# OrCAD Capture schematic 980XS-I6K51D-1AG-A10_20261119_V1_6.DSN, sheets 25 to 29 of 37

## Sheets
25 T05.GROUP4.U5: size D
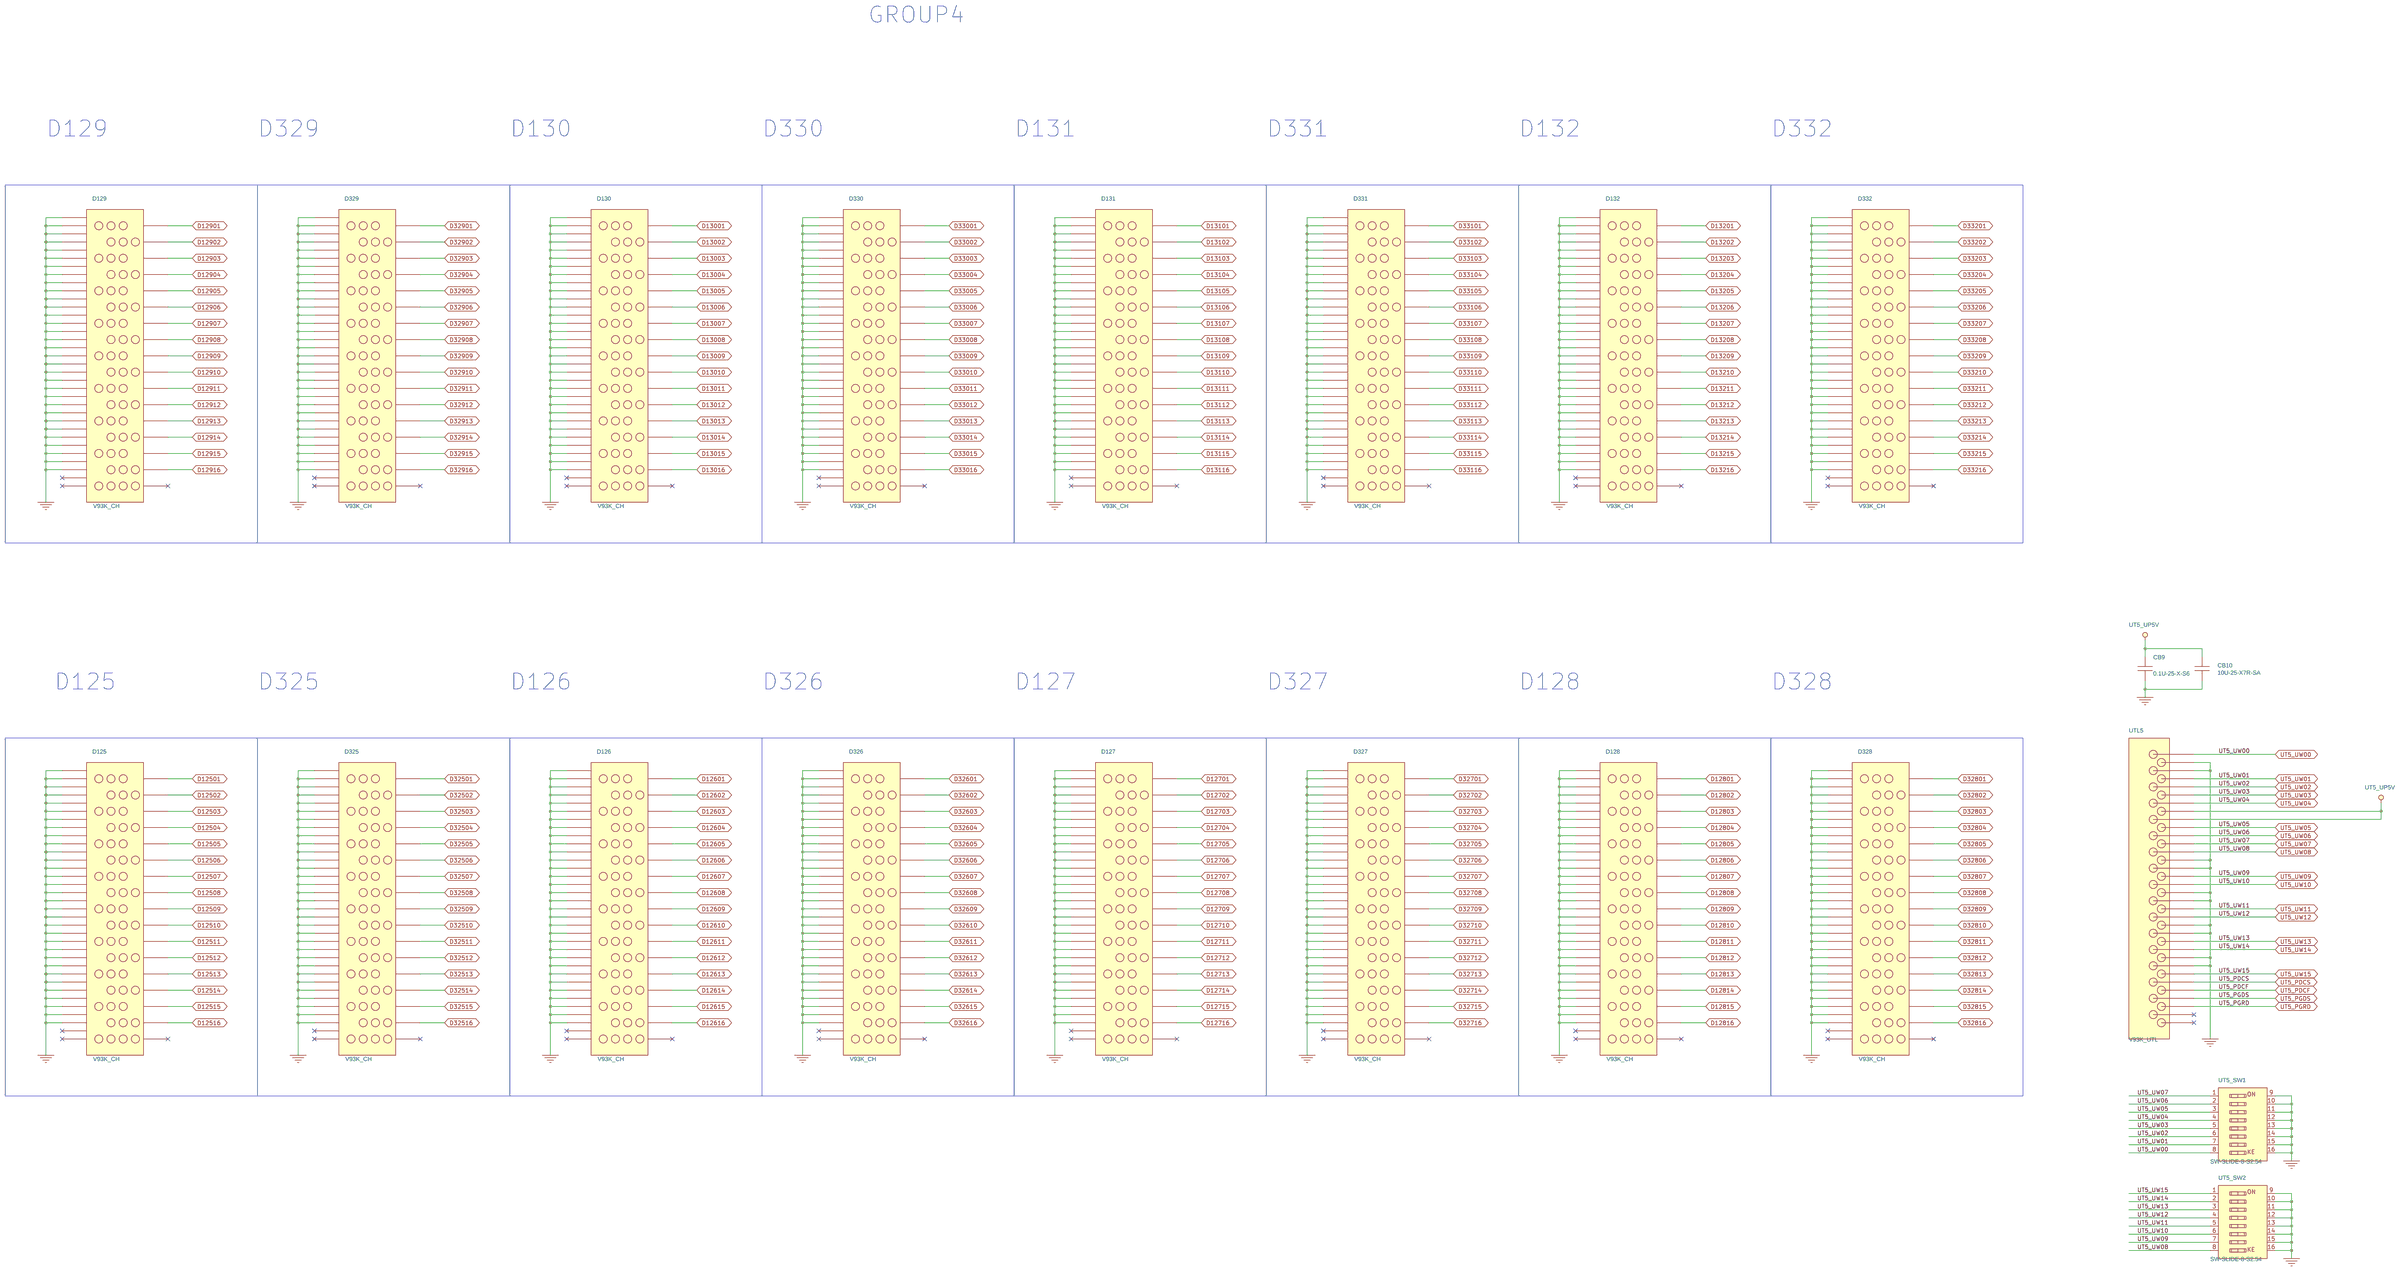
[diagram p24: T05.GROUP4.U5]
26 T06.GROUP5.U6: size D
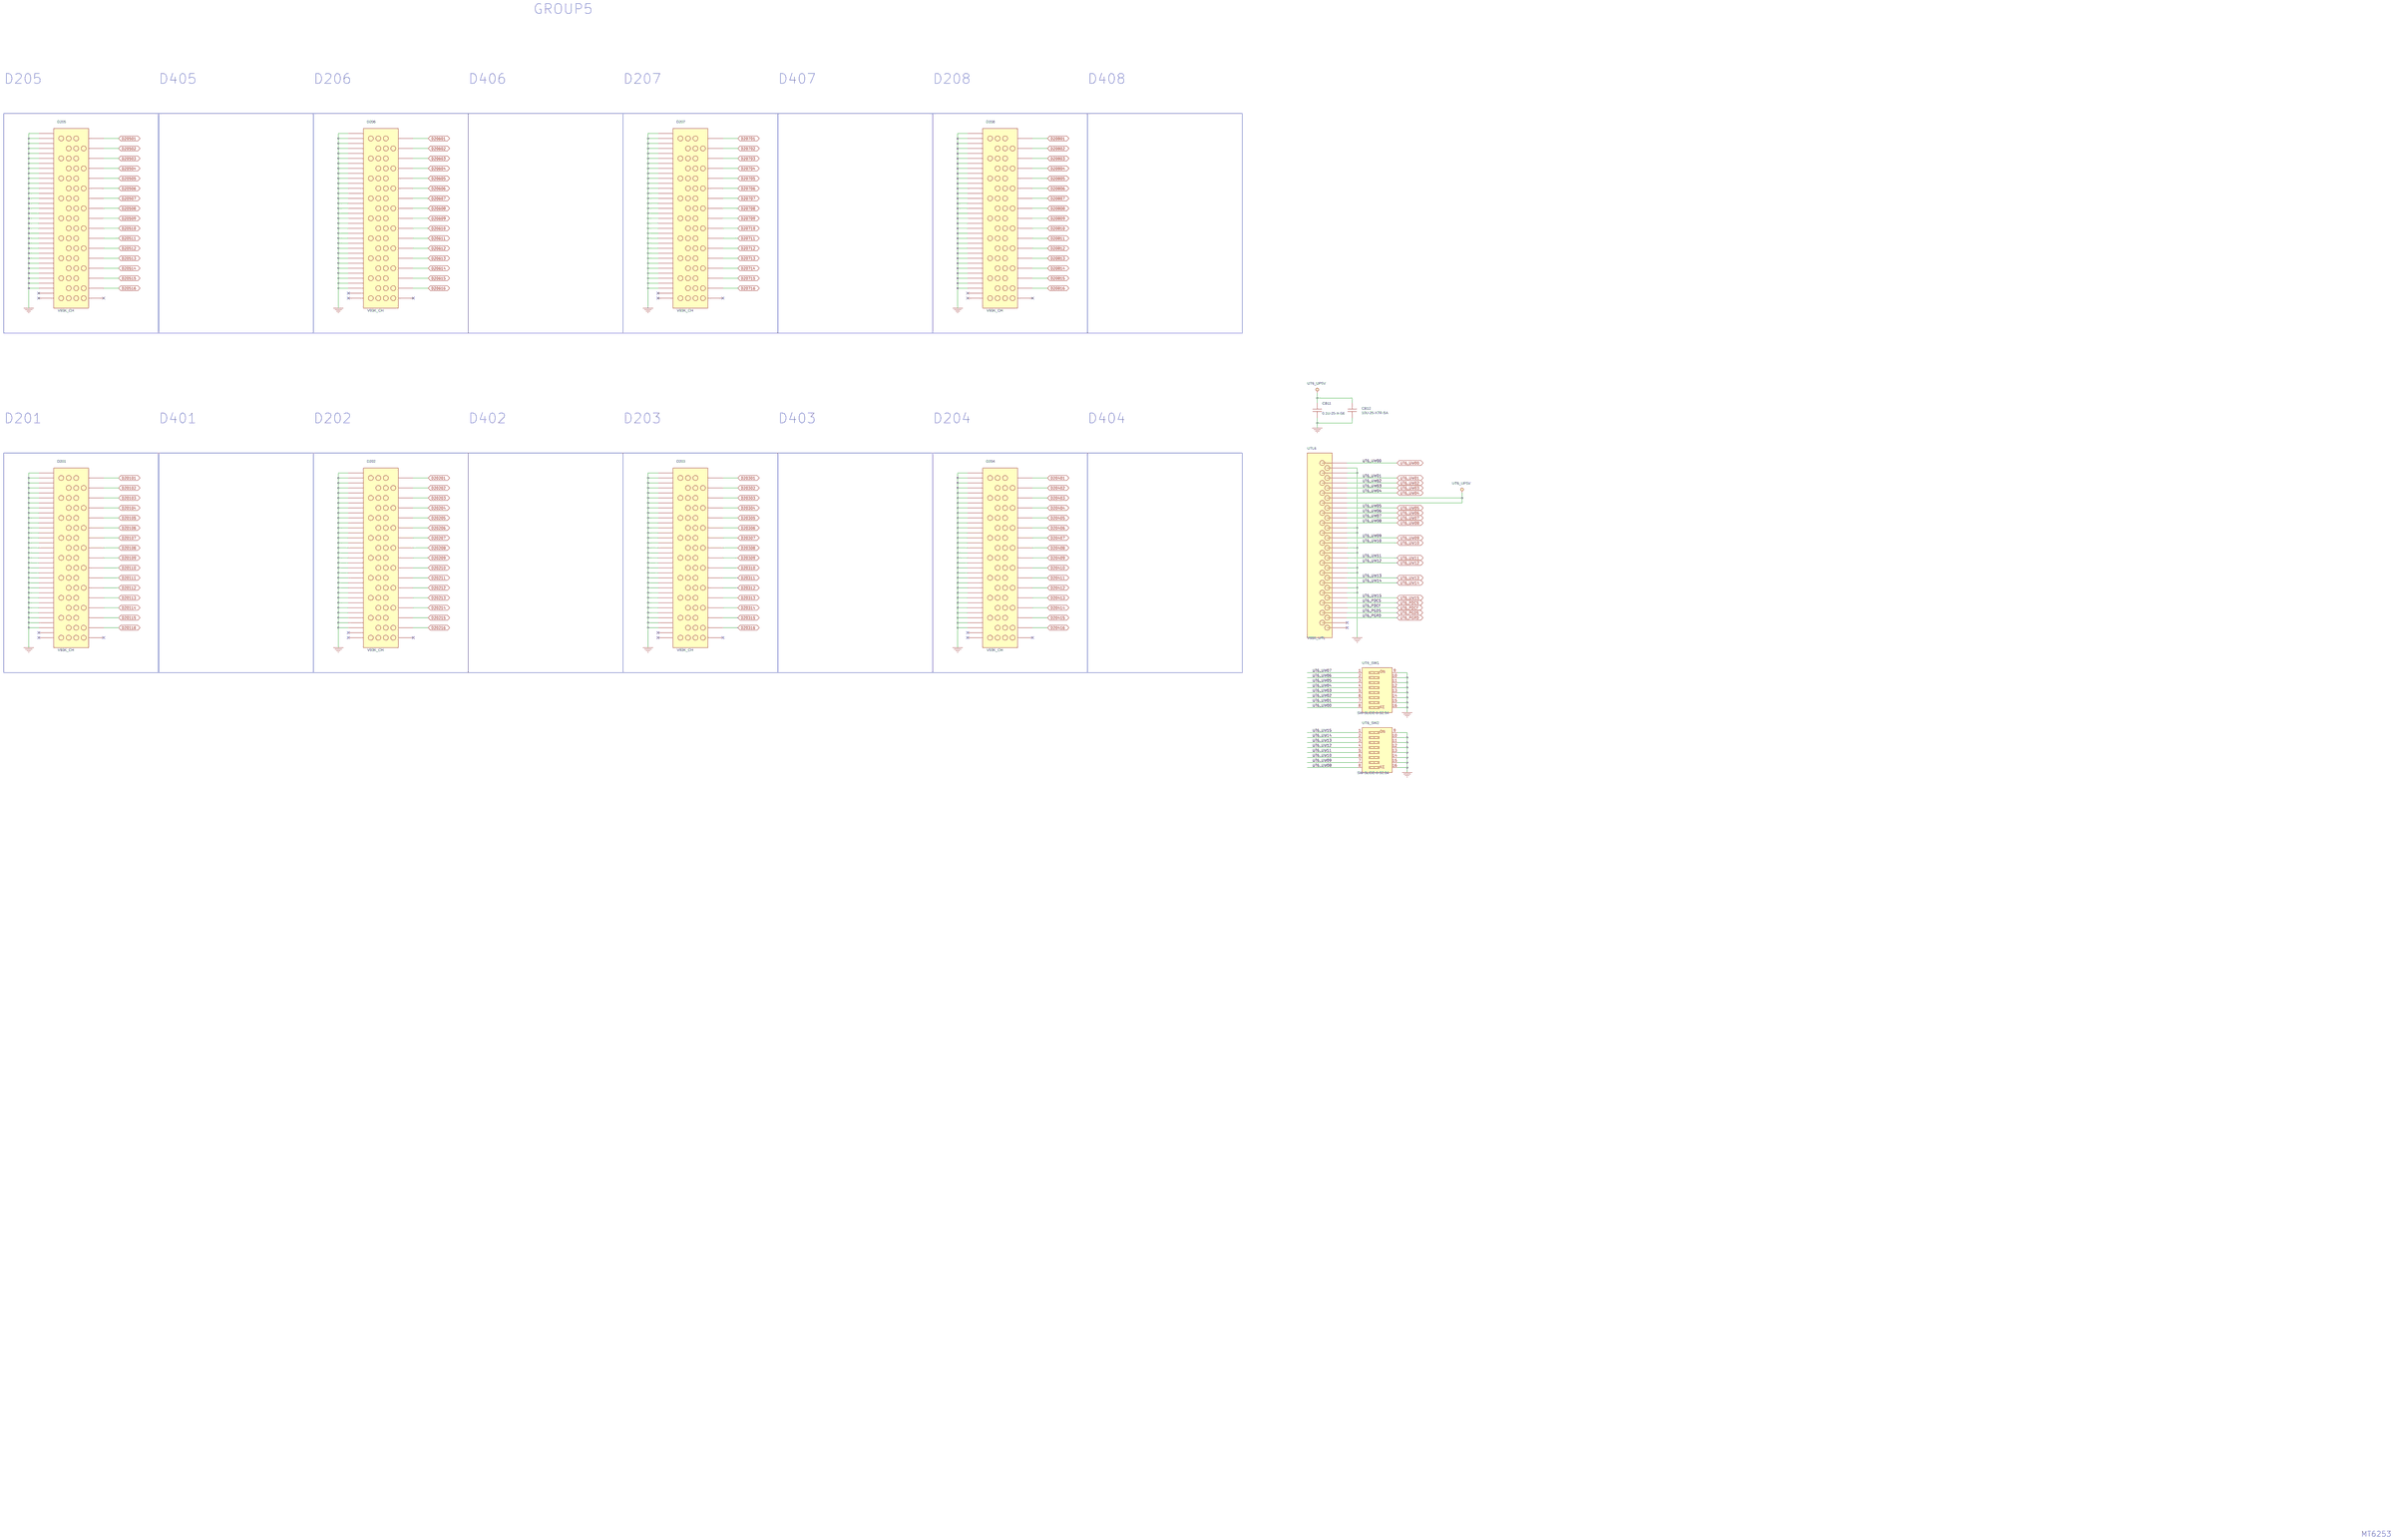
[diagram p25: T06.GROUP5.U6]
27 T07.GROUP6.U7: size D
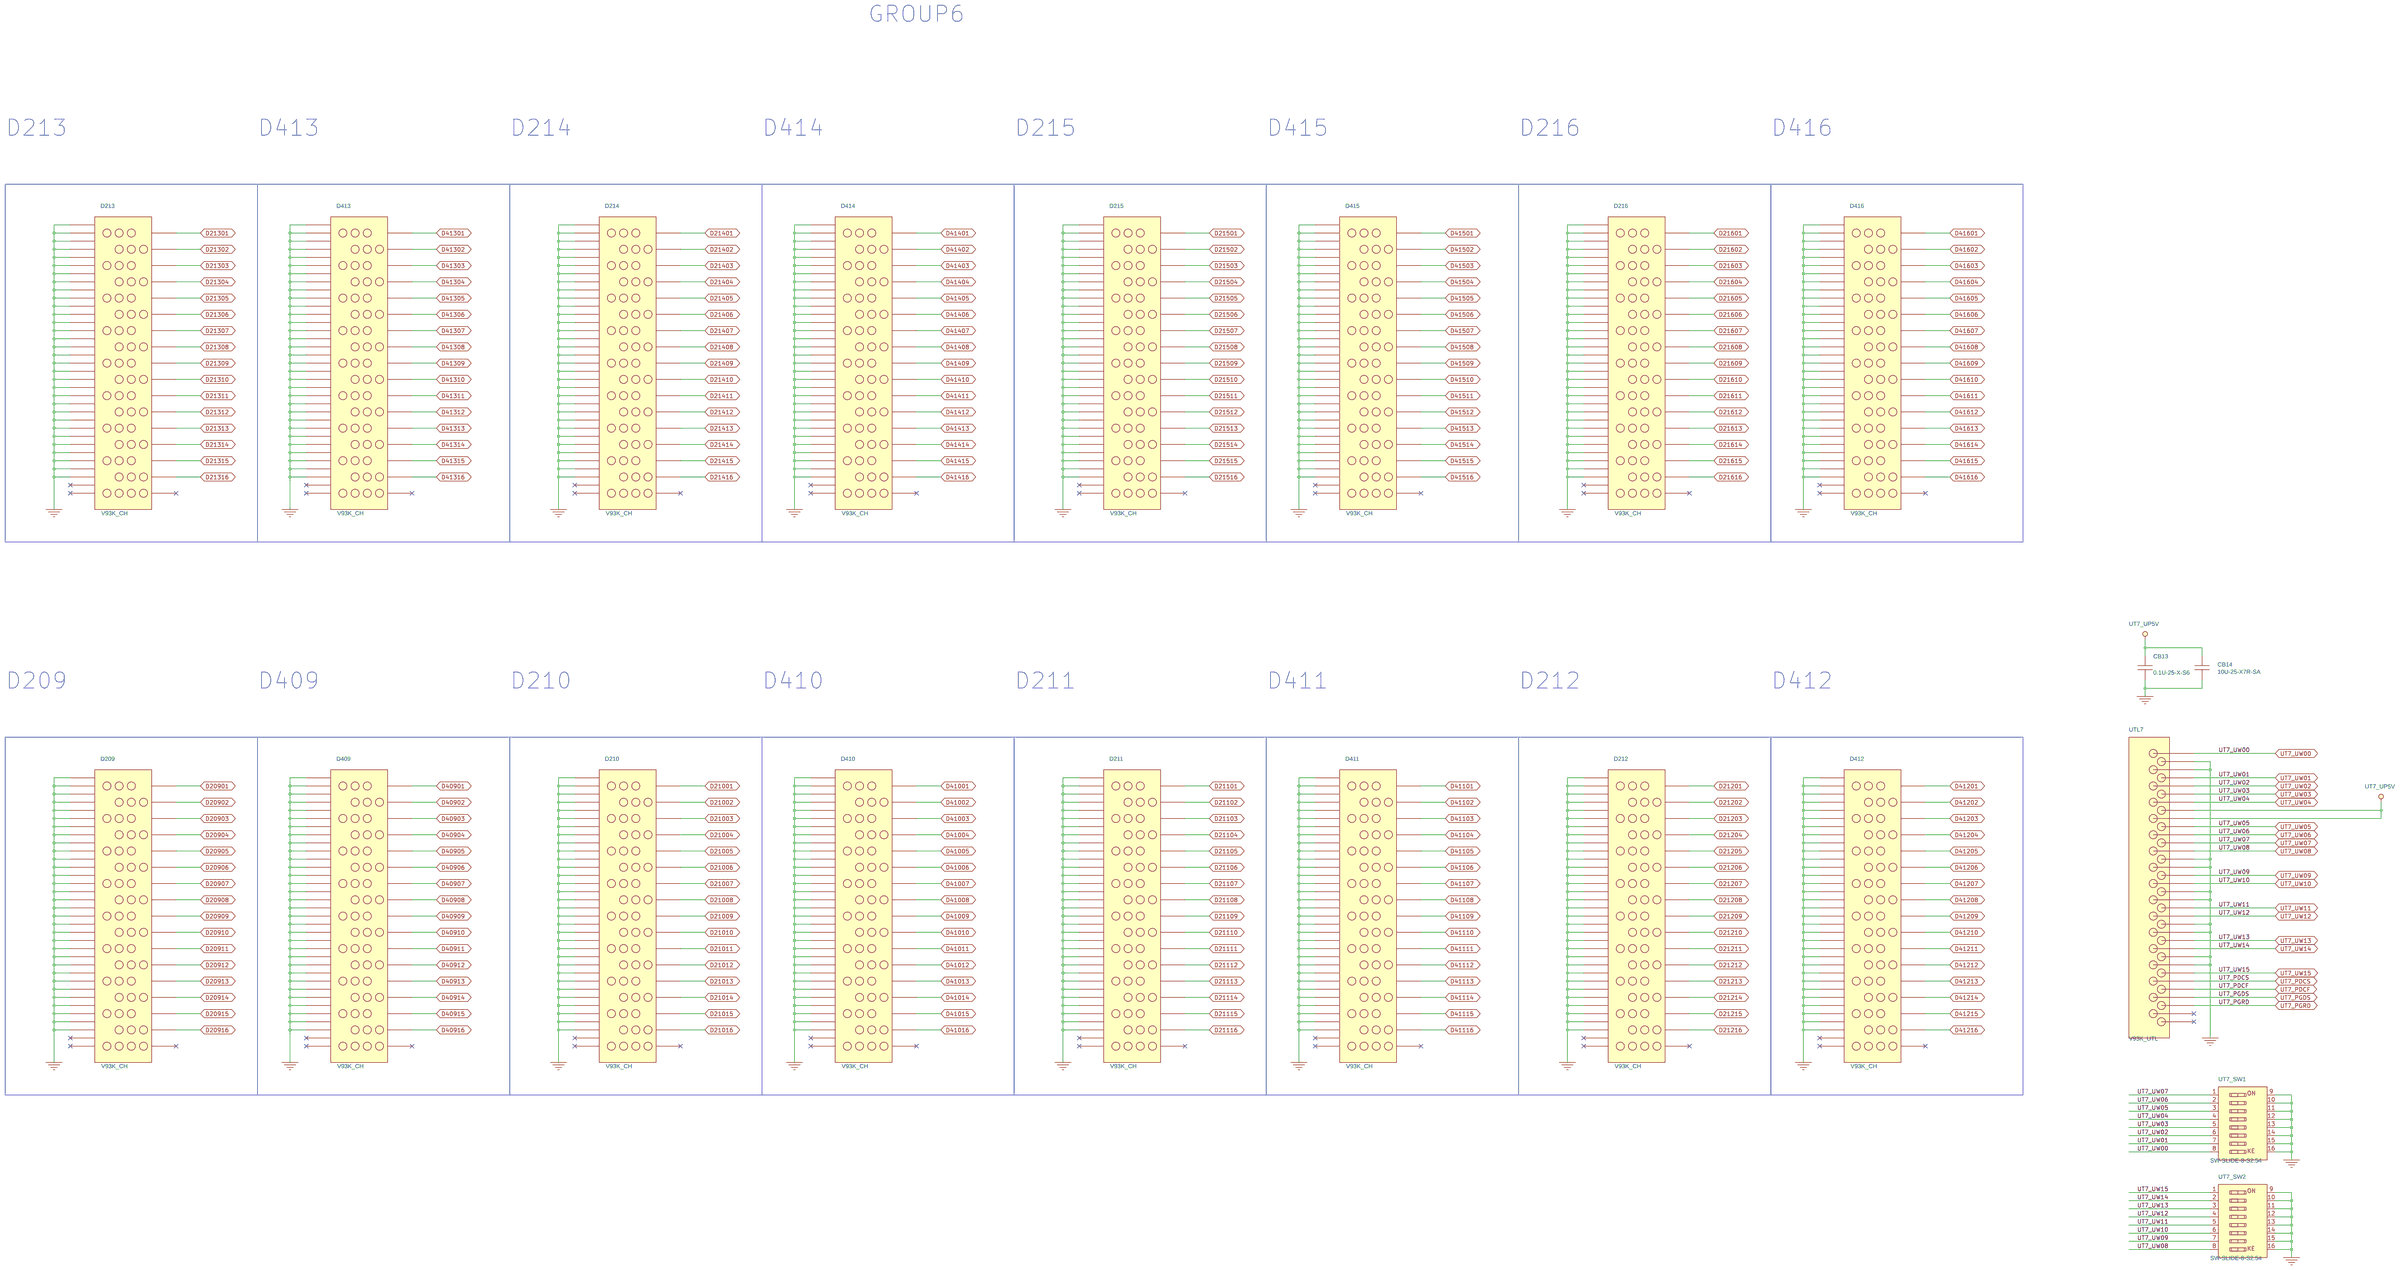
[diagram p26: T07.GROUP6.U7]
28 T08.GROUP7.U8: size D
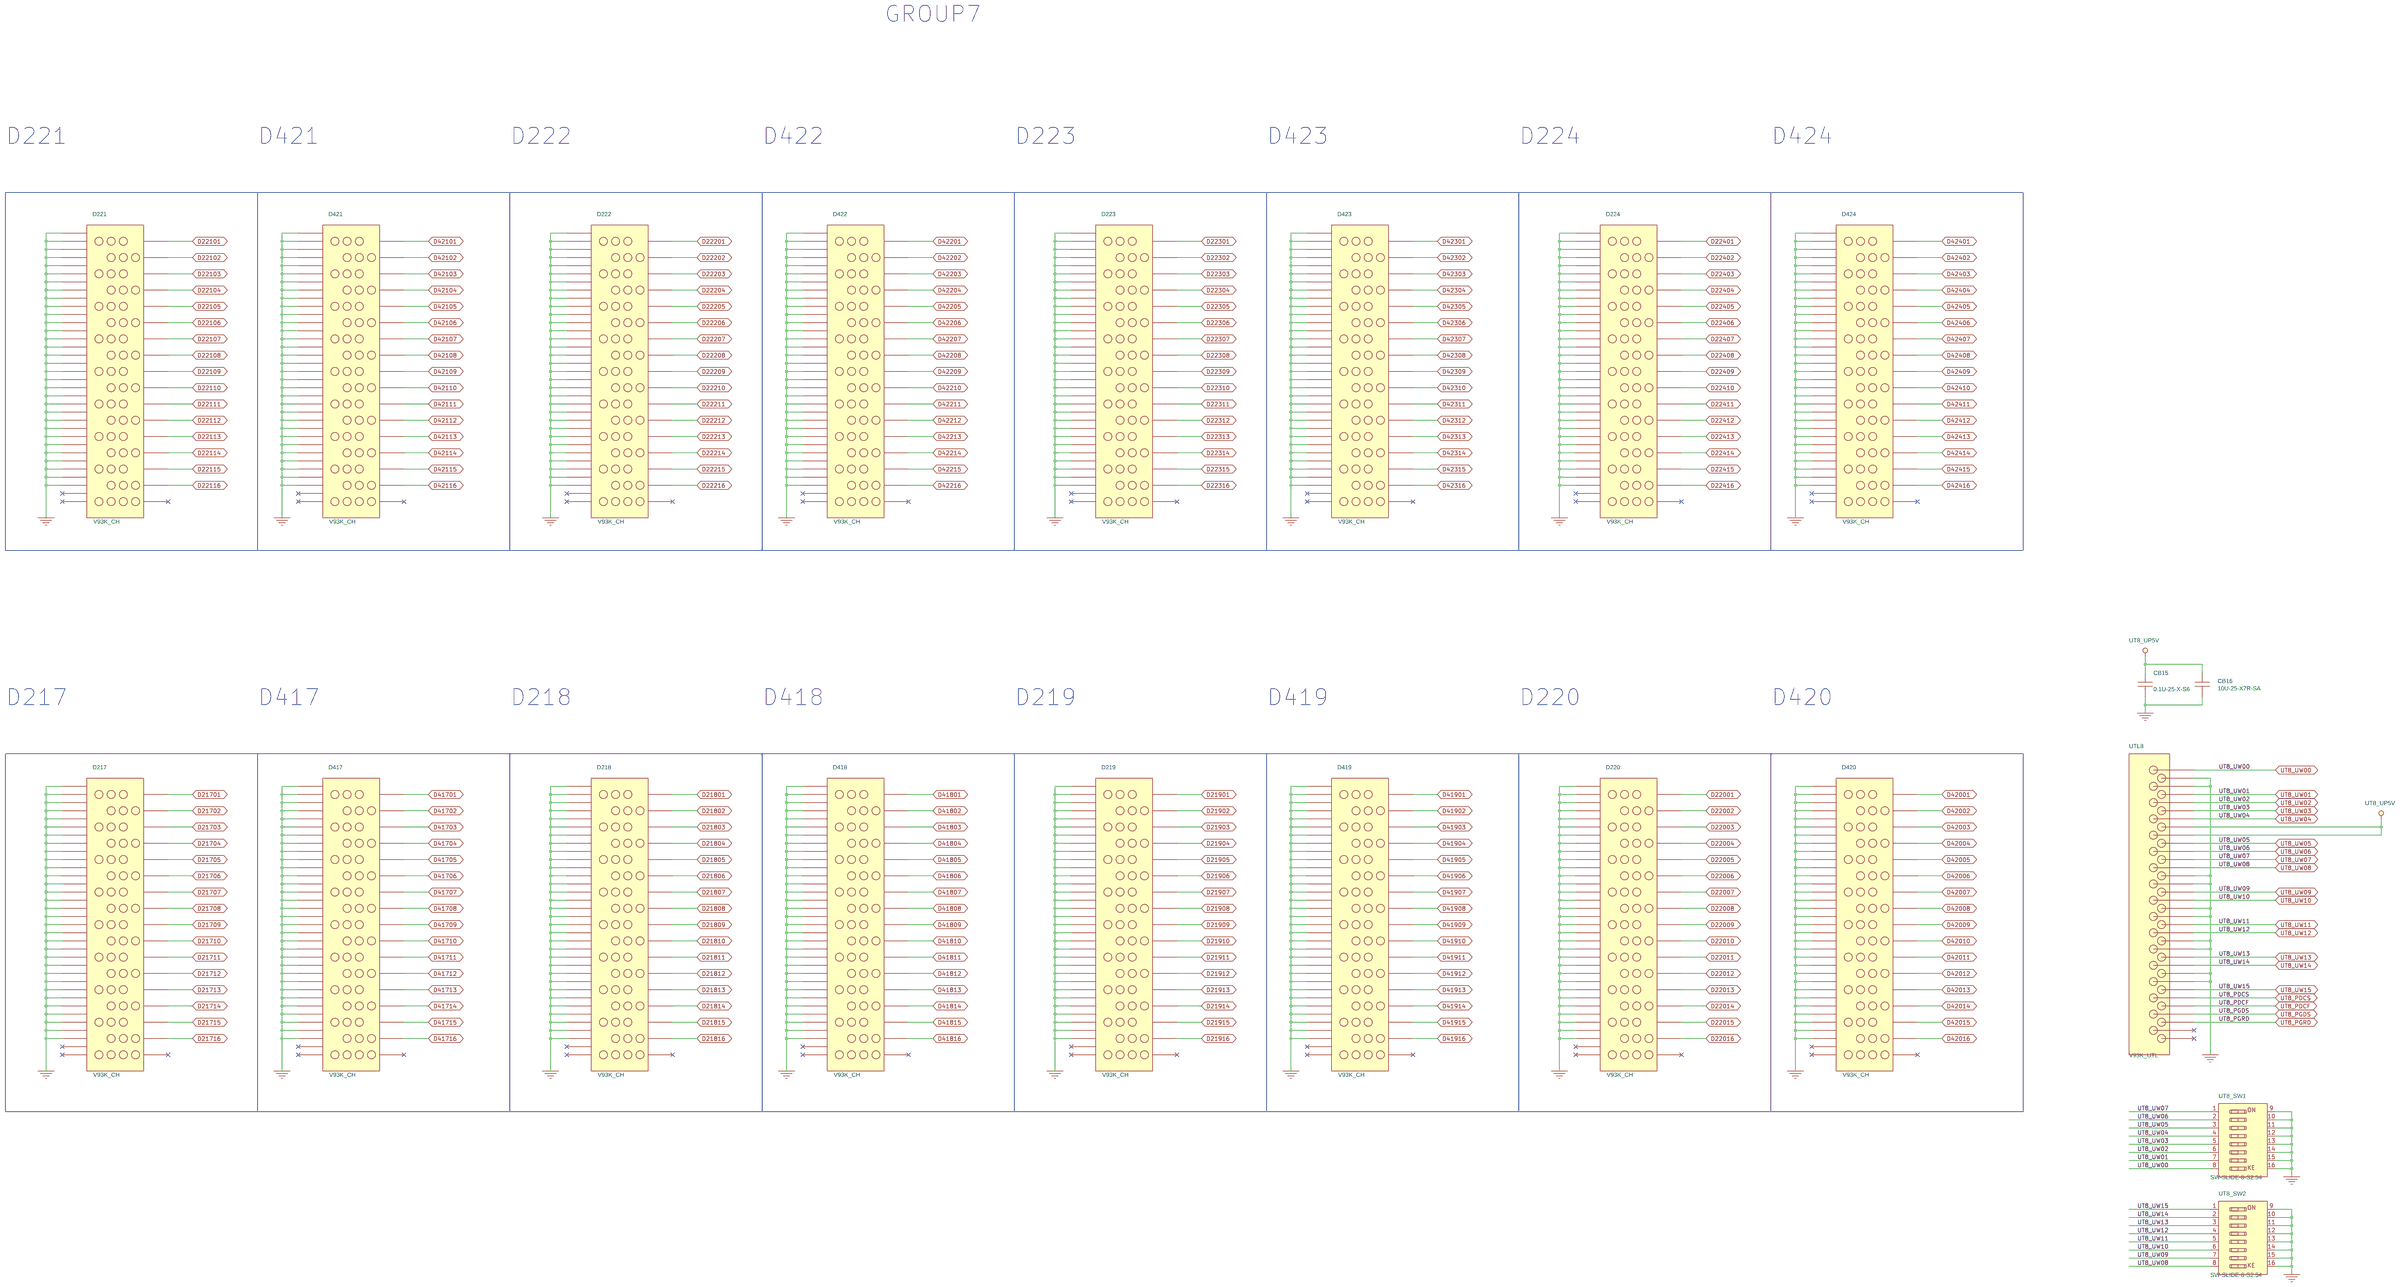
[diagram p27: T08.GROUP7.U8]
29 Z01-Design rule: size A3
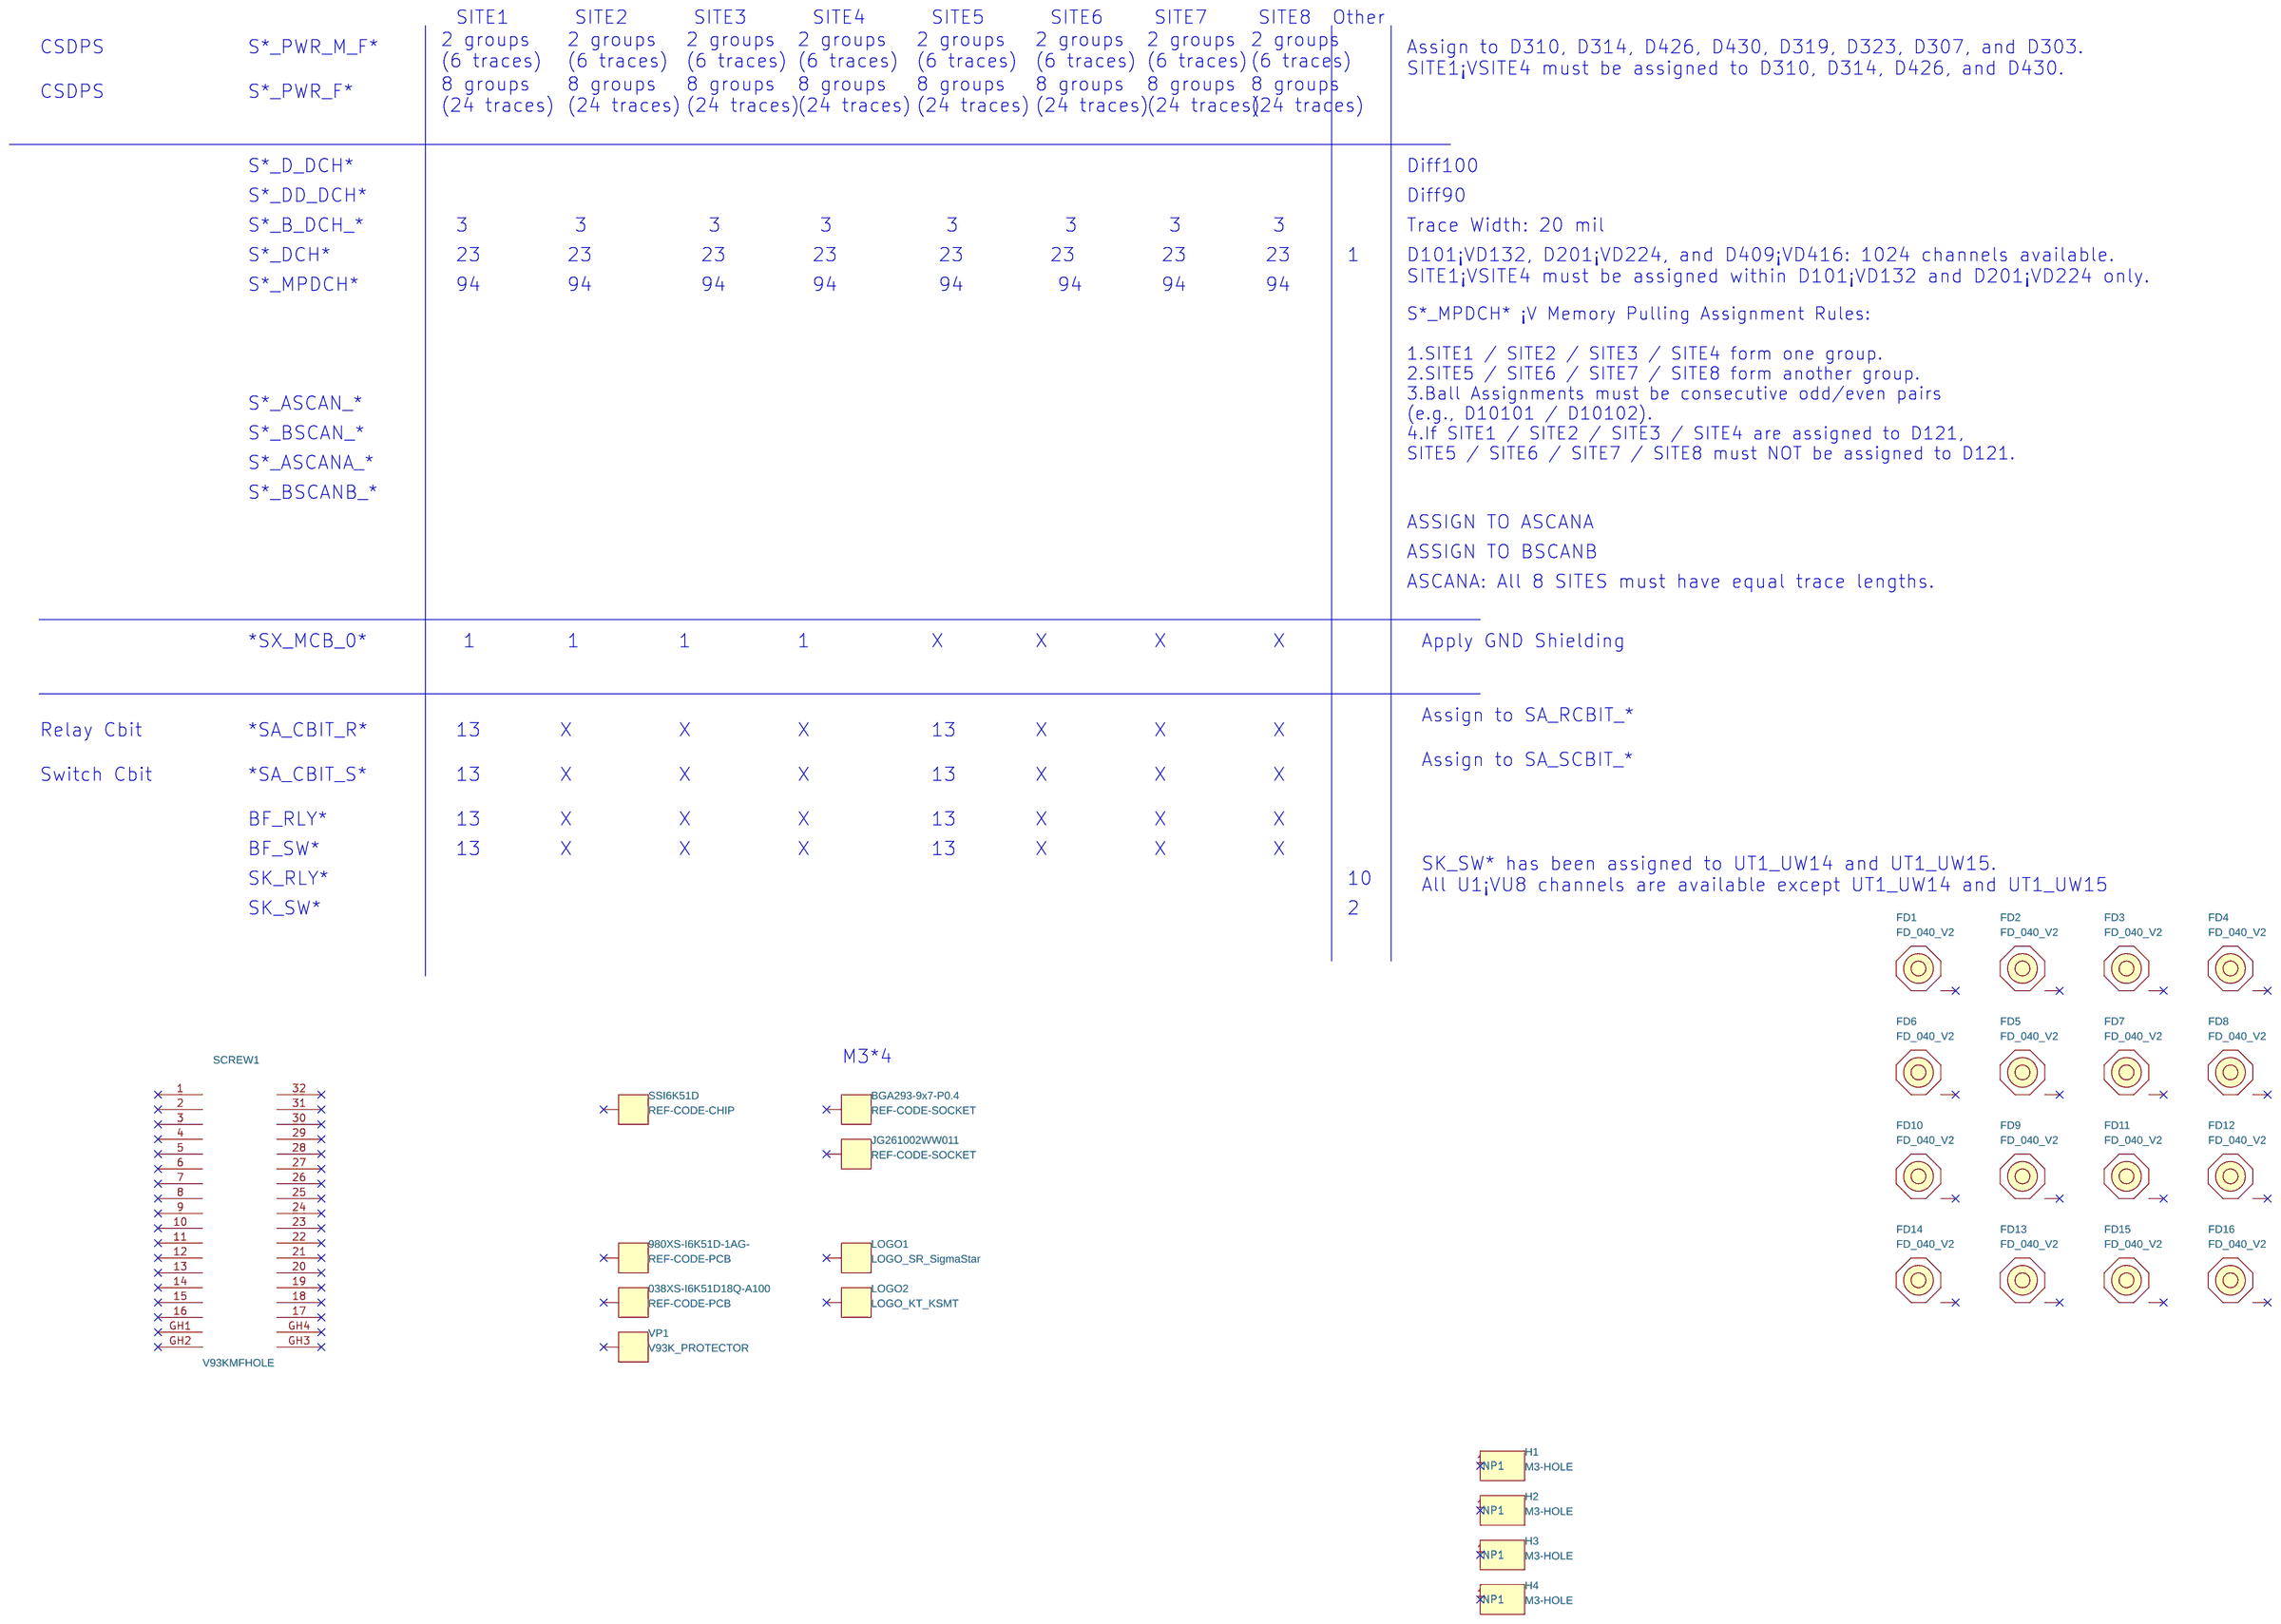
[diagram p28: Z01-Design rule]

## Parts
sheet T05.GROUP4.U5
CB9  0.1U-25-X-S6  [C0603]
CB10  10U-25-X7R-SA  [C1206]
D125  V93K_CH  [PG_VG93K_F_G4D125]
D126  V93K_CH  [PG_VG93K_F_G4D126]
D127  V93K_CH  [PG_VG93K_F_G4D127]
D128  V93K_CH  [PG_VG93K_F_G4D128]
D129  V93K_CH  [PG_VG93K_F_G4D129]
D130  V93K_CH  [PG_VG93K_F_G4D130]
D131  V93K_CH  [PG_VG93K_F_G4D131]
D132  V93K_CH  [PG_VG93K_F_G4D132]
D325  V93K_CH  [PG_VG93K_F_G4D325]
D326  V93K_CH  [PG_VG93K_F_G4D326]
D327  V93K_CH  [PG_VG93K_F_G4D327]
D328  V93K_CH  [PG_VG93K_F_G4D328]
D329  V93K_CH  [PG_VG93K_F_G4D329]
D330  V93K_CH  [PG_VG93K_F_G4D330]
D331  V93K_CH  [PG_VG93K_F_G4D331]
D332  V93K_CH  [PG_VG93K_F_G4D332]
UT5_SW1  SW-SLIDE-8-S2.54  [SW8X2_2P54MM_16P_SMD]
UT5_SW2  SW-SLIDE-8-S2.54  [SW8X2_2P54MM_16P_SMD]
UTL5  V93K_UTL  [PG_VG93K_F_G4UTI5]
sheet T06.GROUP5.U6
CB11  0.1U-25-X-S6  [C0603]
CB12  10U-25-X7R-SA  [C1206]
D201  V93K_CH  [PG_VG93K_F_G5D201]
D202  V93K_CH  [PG_VG93K_F_G5D202]
D203  V93K_CH  [PG_VG93K_F_G5D203]
D204  V93K_CH  [PG_VG93K_F_G5D204]
D205  V93K_CH  [PG_VG93K_F_G5D205]
D206  V93K_CH  [PG_VG93K_F_G5D206]
D207  V93K_CH  [PG_VG93K_F_G5D207]
D208  V93K_CH  [PG_VG93K_F_G5D208]
UT6_SW1  SW-SLIDE-8-S2.54  [SW8X2_2P54MM_16P_SMD]
UT6_SW2  SW-SLIDE-8-S2.54  [SW8X2_2P54MM_16P_SMD]
UTL6  V93K_UTL  [PG_VG93K_F_G5UTI6]
sheet T07.GROUP6.U7
CB13  0.1U-25-X-S6  [C0603]
CB14  10U-25-X7R-SA  [C1206]
D209  V93K_CH  [PG_VG93K_F_G6D209]
D210  V93K_CH  [PG_VG93K_F_G6D210]
D211  V93K_CH  [PG_VG93K_F_G6D211]
D212  V93K_CH  [PG_VG93K_F_G6D212]
D213  V93K_CH  [PG_VG93K_F_G6D213]
D214  V93K_CH  [PG_VG93K_F_G6D214]
D215  V93K_CH  [PG_VG93K_F_G6D215]
D216  V93K_CH  [PG_VG93K_F_G6D216]
D409  V93K_CH  [PG_VG93K_F_G6D409]
D410  V93K_CH  [PG_VG93K_F_G6D410]
D411  V93K_CH  [PG_VG93K_F_G6D411]
D412  V93K_CH  [PG_VG93K_F_G6D412]
D413  V93K_CH  [PG_VG93K_F_G6D413]
D414  V93K_CH  [PG_VG93K_F_G6D414]
D415  V93K_CH  [PG_VG93K_F_G6D415]
D416  V93K_CH  [PG_VG93K_F_G6D416]
UT7_SW1  SW-SLIDE-8-S2.54  [SW8X2_2P54MM_16P_SMD]
UT7_SW2  SW-SLIDE-8-S2.54  [SW8X2_2P54MM_16P_SMD]
UTL7  V93K_UTL  [PG_VG93K_F_G6UTI7]
sheet T08.GROUP7.U8
CB15  0.1U-25-X-S6  [C0603]
CB16  10U-25-X7R-SA  [C1206]
D217  V93K_CH  [PG_VG93K_F_G7D217]
D218  V93K_CH  [PG_VG93K_F_G7D218]
D219  V93K_CH  [PG_VG93K_F_G7D219]
D220  V93K_CH  [PG_VG93K_F_G7D220]
D221  V93K_CH  [PG_VG93K_F_G7D221]
D222  V93K_CH  [PG_VG93K_F_G7D222]
D223  V93K_CH  [PG_VG93K_F_G7D223]
D224  V93K_CH  [PG_VG93K_F_G7D224]
D417  V93K_CH  [PG_VG93K_F_G7D417]
D418  V93K_CH  [PG_VG93K_F_G7D418]
D419  V93K_CH  [PG_VG93K_F_G7D419]
D420  V93K_CH  [PG_VG93K_F_G7D420]
D421  V93K_CH  [PG_VG93K_F_G7D421]
D422  V93K_CH  [PG_VG93K_F_G7D422]
D423  V93K_CH  [PG_VG93K_F_G7D423]
D424  V93K_CH  [PG_VG93K_F_G7D424]
UT8_SW1  SW-SLIDE-8-S2.54  [SW8X2_2P54MM_16P_SMD]
UT8_SW2  SW-SLIDE-8-S2.54  [SW8X2_2P54MM_16P_SMD]
UTL8  V93K_UTL  [PG_VG93K_F_G7UTI8]
sheet Z01-Design rule
038XS-I6K51D18Q-A100  REF-CODE-PCB  [PCB_CODE]
980XS-I6K51D-1AG-  REF-CODE-PCB  [PCB_CODE]
BGA293-9x7-P0.4  REF-CODE-SOCKET  [SOCKET_CODE]
FD1  FD_040_V2  [FD_040_V2]
FD2  FD_040_V2  [FD_040_V2]
FD3  FD_040_V2  [FD_040_V2]
FD4  FD_040_V2  [FD_040_V2]
FD5  FD_040_V2  [FD_040_V2]
FD6  FD_040_V2  [FD_040_V2]
FD7  FD_040_V2  [FD_040_V2]
FD8  FD_040_V2  [FD_040_V2]
FD9  FD_040_V2  [FD_040_V2]
FD10  FD_040_V2  [FD_040_V2]
FD11  FD_040_V2  [FD_040_V2]
FD12  FD_040_V2  [FD_040_V2]
FD13  FD_040_V2  [FD_040_V2]
FD14  FD_040_V2  [FD_040_V2]
FD15  FD_040_V2  [FD_040_V2]
FD16  FD_040_V2  [FD_040_V2]
H1  M3-HOLE  [M3_NPTH169]
H2  M3-HOLE  [M3_NPTH169]
H3  M3-HOLE  [M3_NPTH169]
H4  M3-HOLE  [M3_NPTH169]
JG261002WW011  REF-CODE-SOCKET  [SOCKET_CODE]
LOGO1  LOGO_SR_SigmaStar  [LOGO_SR_SigmaStar]
LOGO2  LOGO_KT_KSMT  [LOGO_KT_KSMT]
SCREW1  V93KMFHOLE  [PG_VG93K_F_FULLOUTLINE]
SSI6K51D  REF-CODE-CHIP  [CHIP_CODE]
VP1  V93K_PROTECTOR  [PCB_CODE]

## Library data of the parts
CB9 CB11 CB13 CB15 = 0.1U-25-X-S6
CB10 CB12 CB14 CB16 = 10U-25-X7R-SA
D125-D132 D201-D224 D325-D332 D409-D424 = V93K_CH
UT5_SW1 UT5_SW2 UT6_SW1 UT6_SW2 UT7_SW1 UT7_SW2 UT8_SW1 UT8_SW2 = SW-SLIDE-8-S2.54
UTL5-UTL8 = V93K_UTL
038XS-I6K51D18Q-A100 = REF-CODE-PCB: KAIROSNAME: 038XS-SP510E1XX-A100
980XS-I6K51D-1AG- = REF-CODE-PCB: KAIROSNAME: 980XS-SP510E-1AG-
BGA293-9x7-P0.4 = REF-CODE-SOCKET: KAIROSNAME: BGA536-16x16-P0.65
FD1-FD16 = FD_040_V2
H1-H4 = M3-HOLE
JG261002WW011 = REF-CODE-SOCKET: KAIROSNAME: WW71159860
LOGO1 = LOGO_MS_Morningstar
LOGO2 = LOGO_KT_KSMT
SCREW1 = V93KMFHOLE
SSI6K51D = REF-CODE-CHIP: KAIROSNAME: SP510E
VP1 = V93K_PROTECTOR

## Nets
DGND: D125.A1 D125.A2 D125.A3 D125.A4 D125.A5 D125.A6 D125.A7 D125.A8 D125.A9 D125.A10 D125.A11 D125.A12 D125.A13 D125.A14 D125.A15 D125.A16 D125.B1 D125.B2 D125.B3 D125.B4 D125.B5 D125.B6 D125.B7 D125.B8 D125.B9 D125.B10 D125.B11 D125.B12 D125.B13 D125.B14 D125.B15 D125.B16 D126.A1 D126.A2 D126.A3 D126.A4 D126.A5 D126.A6 D126.A7 D126.A8 D126.A9 D126.A10 D126.A11 D126.A12 D126.A13 D126.A14 D126.A15 D126.A16 D126.B1 D126.B2 D126.B3 D126.B4 D126.B5 D126.B6 D126.B7 D126.B8 D126.B9 D126.B10 D126.B11 D126.B12 D126.B13 D126.B14 D126.B15 D126.B16 D127.A1 D127.A2 D127.A3 D127.A4 D127.A5 D127.A6 D127.A7 D127.A8 D127.A9 D127.A10 D127.A11 D127.A12 D127.A13 D127.A14 D127.A15 D127.A16 D127.B1 D127.B2 D127.B3 D127.B4 D127.B5 D127.B6 D127.B7 D127.B8 D127.B9 D127.B10 D127.B11 D127.B12 D127.B13 D127.B14 D127.B15 D127.B16 D128.A1 D128.A2 D128.A3 D128.A4 D128.A5 D128.A6 D128.A7 D128.A8 D128.A9 D128.A10 D128.A11 D128.A12 D128.A13 D128.A14 D128.A15 D128.A16 D128.B1 D128.B2 D128.B3 D128.B4 D128.B5 D128.B6 D128.B7 D128.B8 D128.B9 D128.B10 D128.B11 D128.B12 D128.B13 D128.B14 D128.B15 D128.B16 D129.A1 D129.A2 D129.A3 D129.A4 D129.A5 D129.A6 D129.A7 D129.A8 D129.A9 D129.A10 D129.A11 D129.A12 D129.A13 D129.A14 D129.A15 D129.A16 D129.B1 D129.B2 D129.B3 D129.B4 D129.B5 D129.B6 D129.B7 D129.B8 D129.B9 D129.B10 D129.B11 D129.B12 D129.B13 D129.B14 D129.B15 D129.B16 D130.A1 D130.A2 D130.A3 D130.A4 D130.A5 D130.A6 D130.A7 D130.A8 D130.A9 D130.A10 D130.A11 D130.A12 D130.A13 D130.A14 D130.A15 D130.A16 D130.B1 D130.B2 D130.B3 D130.B4 D130.B5 D130.B6 D130.B7 D130.B8 D130.B9 D130.B10 D130.B11 D130.B12 D130.B13 D130.B14 D130.B15 D130.B16 D131.A1 D131.A2 D131.A3 D131.A4 D131.A5 D131.A6 D131.A7 D131.A8 D131.A9 D131.A10 D131.A11 D131.A12 D131.A13 D131.A14 D131.A15 D131.A16 D131.B1 D131.B2 D131.B3 D131.B4 D131.B5 D131.B6 D131.B7 D131.B8 D131.B9 D131.B10 D131.B11 D131.B12 D131.B13 D131.B14 D131.B15 D131.B16 D132.A1 D132.A2 D132.A3 D132.A4 D132.A5 D132.A6 D132.A7 D132.A8 D132.A9 D132.A10 D132.A11 D132.A12 D132.A13 D132.A14 D132.A15 D132.A16 D132.B1 D132.B2 D132.B3 D132.B4 D132.B5 D132.B6 D132.B7 D132.B8 D132.B9 D132.B10 D132.B11 D132.B12 D132.B13 D132.B14 D132.B15 D132.B16 D201.A1 D201.A2 D201.A3 D201.A4 D201.A5 D201.A6 D201.A7 D201.A8 D201.A9 D201.A10 D201.A11 D201.A12 D201.A13 D201.A14 D201.A15 D201.A16 D201.B1 D201.B2 D201.B3 D201.B4 D201.B5 D201.B6 D201.B7 D201.B8 D201.B9 D201.B10 D201.B11 D201.B12 D201.B13 D201.B14 D201.B15 D201.B16 D202.A1 D202.A2 D202.A3 D202.A4 D202.A5 D202.A6 D202.A7 D202.A8 D202.A9 D202.A10 D202.A11 D202.A12 D202.A13 D202.A14 D202.A15 D202.A16 D202.B1 D202.B2 D202.B3 D202.B4 D202.B5 D202.B6 D202.B7 D202.B8 D202.B9 D202.B10 D202.B11 D202.B12 D202.B13 D202.B14 D202.B15 D202.B16 D203.A1 D203.A2 D203.A3 D203.A4 D203.A5 D203.A6 D203.A7 D203.A8 D203.A9 D203.A10 D203.A11 D203.A12 D203.A13 D203.A14 D203.A15 D203.A16 D203.B1 D203.B2 D203.B3 D203.B4 D203.B5 D203.B6 D203.B7 D203.B8 D203.B9 D203.B10 D203.B11 D203.B12 D203.B13 D203.B14 D203.B15 D203.B16 D204.A1 D204.A2 D204.A3 D204.A4 D204.A5 D204.A6 D204.A7 D204.A8 D204.A9 D204.A10 D204.A11 D204.A12 D204.A13 D204.A14 D204.A15 D204.A16 D204.B1 D204.B2 D204.B3 D204.B4 D204.B5 D204.B6 D204.B7 D204.B8 D204.B9 D204.B10 D204.B11 D204.B12 D204.B13 D204.B14 D204.B15 D204.B16 D205.A1 D205.A2 D205.A3 D205.A4 D205.A5 D205.A6 D205.A7 D205.A8 D205.A9 D205.A10 D205.A11 D205.A12 D205.A13 D205.A14 D205.A15 D205.A16 D205.B1 D205.B2 D205.B3 D205.B4 D205.B5 D205.B6 D205.B7 D205.B8 D205.B9 D205.B10 D205.B11 D205.B12 D205.B13 D205.B14 D205.B15 D205.B16 D206.A1 D206.A2 D206.A3 D206.A4 D206.A5 D206.A6 D206.A7 D206.A8 D206.A9 D206.A10 D206.A11 D206.A12 D206.A13 D206.A14 D206.A15 D206.A16 D206.B1 D206.B2 D206.B3 D206.B4 D206.B5 D206.B6 D206.B7 D206.B8 D206.B9 D206.B10 D206.B11 D206.B12 D206.B13 D206.B14 D206.B15 D206.B16 D207.A1 D207.A2 D207.A3 D207.A4 D207.A5 D207.A6 D207.A7 D207.A8 D207.A9 D207.A10 D207.A11 D207.A12 D207.A13 D207.A14 D207.A15 D207.A16 D207.B1 D207.B2 D207.B3 D207.B4 D207.B5 D207.B6 D207.B7 D207.B8 D207.B9 D207.B10 D207.B11 D207.B12 D207.B13 D207.B14 D207.B15 D207.B16 D208.A1 D208.A2 D208.A3 D208.A4 D208.A5 D208.A6 D208.A7 D208.A8 D208.A9 D208.A10 D208.A11 D208.A12 D208.A13 D208.A14 D208.A15 D208.A16 D208.B1 D208.B2 D208.B3 D208.B4 D208.B5 D208.B6 D208.B7 D208.B8 D208.B9 D208.B10 D208.B11 D208.B12 D208.B13 D208.B14 D208.B15 D208.B16 D209.A1 D209.A2 D209.A3 D209.A4 D209.A5 D209.A6 D209.A7 D209.A8 D209.A9 D209.A10 D209.A11 D209.A12 D209.A13 D209.A14 D209.A15 D209.A16 D209.B1 D209.B2 D209.B3 D209.B4 D209.B5 D209.B6 D209.B7 D209.B8 D209.B9 D209.B10 D209.B11 D209.B12 D209.B13 D209.B14 D209.B15 D209.B16 D210.A1 D210.A2 D210.A3 D210.A4 D210.A5 D210.A6 D210.A7 D210.A8 D210.A9 D210.A10 D210.A11 D210.A12 D210.A13 D210.A14 D210.A15 D210.A16 D210.B1 D210.B2 D210.B3 D210.B4 D210.B5 D210.B6 D210.B7 D210.B8 D210.B9 D210.B10 D210.B11 D210.B12 D210.B13 D210.B14 D210.B15 D210.B16 D211.A1 D211.A2 D211.A3 D211.A4 D211.A5 D211.A6 D211.A7 D211.A8 D211.A9 D211.A10 D211.A11 D211.A12 D211.A13 D211.A14 D211.A15 D211.A16 D211.B1 D211.B2 D211.B3 D211.B4 D211.B5 D211.B6 D211.B7 D211.B8 D211.B9 D211.B10 D211.B11 D211.B12 D211.B13 D211.B14 D211.B15 D211.B16 D212.A1 D212.A2 D212.A3 D212.A4 D212.A5 D212.A6 D212.A7 D212.A8 D212.A9 D212.A10 D212.A11 D212.A12 D212.A13 D212.A14 D212.A15 D212.A16 D212.B1 D212.B2 D212.B3 D212.B4 D212.B5 D212.B6 D212.B7 D212.B8 D212.B9 D212.B10 D212.B11 D212.B12 D212.B13 D212.B14 D212.B15 D212.B16 D213.A1 D213.A2 D213.A3 D213.A4 D213.A5 D213.A6 D213.A7 D213.A8 D213.A9 D213.A10 D213.A11 D213.A12 D213.A13 D213.A14 D213.A15 D213.A16 D213.B1 D213.B2 D213.B3 D213.B4 D213.B5 D213.B6 D213.B7 D213.B8 D213.B9 D213.B10 D213.B11 D213.B12 D213.B13 D213.B14 D213.B15 D213.B16 D214.A1 D214.A2 D214.A3 D214.A4 D214.A5 D214.A6 D214.A7 D214.A8 D214.A9 D214.A10 D214.A11 D214.A12 D214.A13 D214.A14 D214.A15 D214.A16 D214.B1 D214.B2 D214.B3 D214.B4 D214.B5 D214.B6 D214.B7 D214.B8 D214.B9 D214.B10 D214.B11 D214.B12 D214.B13 D214.B14 D214.B15 D214.B16 D215.A1 D215.A2 D215.A3 D215.A4 D215.A5 D215.A6 D215.A7 D215.A8 D215.A9 D215.A10 D215.A11 D215.A12 D215.A13 D215.A14 D215.A15 D215.A16 D215.B1 D215.B2 D215.B3 D215.B4 D215.B5 D215.B6 D215.B7 D215.B8 D215.B9 D215.B10 D215.B11 D215.B12 D215.B13 D215.B14 D215.B15 D215.B16 D216.A1 D216.A2 D216.A3 D216.A4 D216.A5 D216.A6 D216.A7 D216.A8 D216.A9 D216.A10 D216.A11 D216.A12 D216.A13 D216.A14 D216.A15 D216.A16 D216.B1 D216.B2 D216.B3 D216.B4 D216.B5 D216.B6 D216.B7 D216.B8 D216.B9 D216.B10 D216.B11 D216.B12 D216.B13 D216.B14 D216.B15 D216.B16 D217.A1 D217.A2 D217.A3 D217.A4 D217.A5 D217.A6 D217.A7 D217.A8 D217.A9 D217.A10 D217.A11 D217.A12 D217.A13 D217.A14 D217.A15 D217.A16 D217.B1 D217.B2 D217.B3 D217.B4 D217.B5 D217.B6 D217.B7 D217.B8 D217.B9 D217.B10 D217.B11 D217.B12 D217.B13 D217.B14 D217.B15 D217.B16 D218.A1 D218.A2 D218.A3 D218.A4 D218.A5 D218.A6 D218.A7 D218.A8 D218.A9 D218.A10 D218.A11 D218.A12 D218.A13 D218.A14 D218.A15 D218.A16 D218.B1 D218.B2 D218.B3 D218.B4 D218.B5 D218.B6 D218.B7 D218.B8 D218.B9 D218.B10 D218.B11 D218.B12 D218.B13 D218.B14 D218.B15 D218.B16 D219.A1 D219.A2 D219.A3 D219.A4 D219.A5 D219.A6 D219.A7 D219.A8 D219.A9 D219.A10 D219.A11 D219.A12 D219.A13 D219.A14 D219.A15 D219.A16 D219.B1 D219.B2 D219.B3 D219.B4 D219.B5 D219.B6 D219.B7 D219.B8 D219.B9 D219.B10 D219.B11 D219.B12 D219.B13 D219.B14 D219.B15 D219.B16 D220.A1 D220.A2 D220.A3 D220.A4 D220.A5 D220.A6 D220.A7 D220.A8 D220.A9 D220.A10 D220.A11 D220.A12 D220.A13 D220.A14 D220.A15 D220.A16 D220.B1 D220.B2 D220.B3 D220.B4 D220.B5 D220.B6 D220.B7 D220.B8 D220.B9 D220.B10 D220.B11 D220.B12 D220.B13 D220.B14 D220.B15 D220.B16 D221.A1 D221.A2 D221.A3 D221.A4 D221.A5 D221.A6 D221.A7 D221.A8 D221.A9 D221.A10 D221.A11 D221.A12 D221.A13 D221.A14 D221.A15 D221.A16 D221.B1 D221.B2 D221.B3 D221.B4 D221.B5 D221.B6 D221.B7 D221.B8 D221.B9 D221.B10 D221.B11 D221.B12 D221.B13 D221.B14 D221.B15 D221.B16 D222.A1 D222.A2 D222.A3 D222.A4 D222.A5 D222.A6 D222.A7 D222.A8 D222.A9 D222.A10 D222.A11 D222.A12 D222.A13 D222.A14 D222.A15 D222.A16 D222.B1 D222.B2 D222.B3 D222.B4 D222.B5 D222.B6 D222.B7 D222.B8 D222.B9 D222.B10 D222.B11 D222.B12 D222.B13 D222.B14 D222.B15 D222.B16 D223.A1 D223.A2 D223.A3 D223.A4 D223.A5 D223.A6 D223.A7 D223.A8 D223.A9 D223.A10 D223.A11 D223.A12 D223.A13 D223.A14 D223.A15 D223.A16 D223.B1 D223.B2 D223.B3 D223.B4 D223.B5 D223.B6 D223.B7 D223.B8 D223.B9 D223.B10 D223.B11 D223.B12 D223.B13 D223.B14 D223.B15 D223.B16 D224.A1 D224.A2 D224.A3 D224.A4 D224.A5 D224.A6 D224.A7 D224.A8 D224.A9 D224.A10 D224.A11 D224.A12 D224.A13 D224.A14 D224.A15 D224.A16 D224.B1 D224.B2 D224.B3 D224.B4 D224.B5 D224.B6 D224.B7 D224.B8 D224.B9 D224.B10 D224.B11 D224.B12 D224.B13 D224.B14 D224.B15 D224.B16 D325.A1 D325.A2 D325.A3 D325.A4 D325.A5 D325.A6 D325.A7 D325.A8 D325.A9 D325.A10 D325.A11 D325.A12 D325.A13 D325.A14 D325.A15 D325.A16 D325.B1 D325.B2 D325.B3 D325.B4 D325.B5 D325.B6 D325.B7 D325.B8 D325.B9 D325.B10 D325.B11 D325.B12 D325.B13 D325.B14 D325.B15 D325.B16 D326.A1 D326.A2 D326.A3 D326.A4 D326.A5 D326.A6 D326.A7 D326.A8 D326.A9 D326.A10 D326.A11 D326.A12 D326.A13 D326.A14 D326.A15 D326.A16 D326.B1 D326.B2 D326.B3 D326.B4 D326.B5 D326.B6 D326.B7 D326.B8 D326.B9 D326.B10 D326.B11 D326.B12 D326.B13 D326.B14 D326.B15 D326.B16 D327.A1 D327.A2 D327.A3 D327.A4 D327.A5 D327.A6 D327.A7 D327.A8 D327.A9 D327.A10 D327.A11 D327.A12 D327.A13 D327.A14 D327.A15 D327.A16 D327.B1 D327.B2 D327.B3 D327.B4 D327.B5 D327.B6 D327.B7 D327.B8 D327.B9 D327.B10 D327.B11 D327.B12 D327.B13 D327.B14 D327.B15 D327.B16 D328.A1 D328.A2 D328.A3 D328.A4 D328.A5 D328.A6 D328.A7 D328.A8 D328.A9 D328.A10 D328.A11 D328.A12 D328.A13 D328.A14 D328.A15 D328.A16 D328.B1 D328.B2 D328.B3 D328.B4 D328.B5 D328.B6 D328.B7 D328.B8 D328.B9 D328.B10 D328.B11 D328.B12 D328.B13 D328.B14 D328.B15 D328.B16 D329.A1 D329.A2 D329.A3 D329.A4 D329.A5 D329.A6 D329.A7 D329.A8 D329.A9 D329.A10 D329.A11 D329.A12 D329.A13 D329.A14 D329.A15 D329.A16 D329.B1 D329.B2 D329.B3 D329.B4 D329.B5 D329.B6 D329.B7 D329.B8 D329.B9 D329.B10 D329.B11 D329.B12 D329.B13 D329.B14 D329.B15 D329.B16 D330.A1 D330.A2 D330.A3 D330.A4 D330.A5 D330.A6 D330.A7 D330.A8 D330.A9 D330.A10 D330.A11 D330.A12 D330.A13 D330.A14 D330.A15 D330.A16 D330.B1 D330.B2 D330.B3 D330.B4 D330.B5 D330.B6 D330.B7 D330.B8 D330.B9 D330.B10 D330.B11 D330.B12 D330.B13 D330.B14 D330.B15 D330.B16 D331.A1 D331.A2 D331.A3 D331.A4 D331.A5 D331.A6 D331.A7 D331.A8 D331.A9 D331.A10 D331.A11 D331.A12 D331.A13 D331.A14 D331.A15 D331.A16 D331.B1 D331.B2 D331.B3 D331.B4 D331.B5 D331.B6 D331.B7 D331.B8 D331.B9 D331.B10 D331.B11 D331.B12 D331.B13 D331.B14 D331.B15 D331.B16 D332.A1 D332.A2 D332.A3 D332.A4 D332.A5 D332.A6 D332.A7 D332.A8 D332.A9 D332.A10 D332.A11 D332.A12 D332.A13 D332.A14 D332.A15 D332.A16 D332.B1 D332.B2 D332.B3 D332.B4 D332.B5 D332.B6 D332.B7 D332.B8 D332.B9 D332.B10 D332.B11 D332.B12 D332.B13 D332.B14 D332.B15 D332.B16 D409.A1 D409.A2 D409.A3 D409.A4 D409.A5 D409.A6 D409.A7 D409.A8 D409.A9 D409.A10 D409.A11 D409.A12 D409.A13 D409.A14 D409.A15 D409.A16 D409.B1 D409.B2 D409.B3 D409.B4 D409.B5 D409.B6 D409.B7 D409.B8 D409.B9 D409.B10 D409.B11 D409.B12 D409.B13 D409.B14 D409.B15 D409.B16 D410.A1 D410.A2 D410.A3 D410.A4 D410.A5 D410.A6 D410.A7 D410.A8 D410.A9 D410.A10 D410.A11 D410.A12 D410.A13 D410.A14 D410.A15 D410.A16 D410.B1 D410.B2 D410.B3 D410.B4 D410.B5 D410.B6 D410.B7 D410.B8 D410.B9 D410.B10 D410.B11 D410.B12 D410.B13 D410.B14 D410.B15 D410.B16 D411.A1 D411.A2 D411.A3 D411.A4 D411.A5 D411.A6 D411.A7 D411.A8 D411.A9 D411.A10 D411.A11 D411.A12 D411.A13 D411.A14 D411.A15 D411.A16 D411.B1 D411.B2 D411.B3 D411.B4 D411.B5 D411.B6 D411.B7 D411.B8 D411.B9 D411.B10 D411.B11 D411.B12 D411.B13 D411.B14 D411.B15 D411.B16 D412.A1 D412.A2 D412.A3 D412.A4 D412.A5 D412.A6 D412.A7 D412.A8 D412.A9 D412.A10 D412.A11 D412.A12 D412.A13 D412.A14 D412.A15 D412.A16 D412.B1 D412.B2 D412.B3 D412.B4 D412.B5 D412.B6 D412.B7 D412.B8 D412.B9 D412.B10 D412.B11 D412.B12 D412.B13 D412.B14 D412.B15 D412.B16 D413.A1 D413.A2 D413.A3 D413.A4 D413.A5 D413.A6 D413.A7 D413.A8 D413.A9 D413.A10 D413.A11 D413.A12 D413.A13 D413.A14 D413.A15 D413.A16 D413.B1 D413.B2 D413.B3 D413.B4 D413.B5 D413.B6 D413.B7 D413.B8 D413.B9 D413.B10 D413.B11 D413.B12 D413.B13 D413.B14 D413.B15 D413.B16 D414.A1 D414.A2 D414.A3 D414.A4 D414.A5 D414.A6 D414.A7 D414.A8 D414.A9 D414.A10 D414.A11 D414.A12 D414.A13 D414.A14 D414.A15 D414.A16 D414.B1 D414.B2 D414.B3 D414.B4 D414.B5 D414.B6 D414.B7 D414.B8 D414.B9 D414.B10 D414.B11 D414.B12 D414.B13 D414.B14 D414.B15 D414.B16 D415.A1 D415.A2 D415.A3 D415.A4 D415.A5 D415.A6 D415.A7 D415.A8 D415.A9 D415.A10 D415.A11 D415.A12 D415.A13 D415.A14 D415.A15 D415.A16 D415.B1 D415.B2 D415.B3 D415.B4 D415.B5 D415.B6 D415.B7 D415.B8 D415.B9 D415.B10 D415.B11 D415.B12 D415.B13 D415.B14 D415.B15 D415.B16 D416.A1 D416.A2 D416.A3 D416.A4 D416.A5 D416.A6 D416.A7 D416.A8 D416.A9 D416.A10 D416.A11 D416.A12 D416.A13 D416.A14 D416.A15 D416.A16 D416.B1 D416.B2 D416.B3 D416.B4 D416.B5 D416.B6 D416.B7 D416.B8 D416.B9 D416.B10 D416.B11 D416.B12 D416.B13 D416.B14 D416.B15 D416.B16 D417.A1 D417.A2 D417.A3 D417.A4 D417.A5 D417.A6 D417.A7 D417.A8 D417.A9 D417.A10 D417.A11 D417.A12 D417.A13 D417.A14 D417.A15 D417.A16 D417.B1 D417.B2 D417.B3 D417.B4 D417.B5 D417.B6 D417.B7 D417.B8 D417.B9 D417.B10 D417.B11 D417.B12 D417.B13 D417.B14 D417.B15 D417.B16 D418.A1 D418.A2 D418.A3 D418.A4 D418.A5 D418.A6 D418.A7 D418.A8 D418.A9 D418.A10 D418.A11 D418.A12 D418.A13 D418.A14 D418.A15 D418.A16 D418.B1 D418.B2 D418.B3 D418.B4 D418.B5 D418.B6 D418.B7 D418.B8 D418.B9 D418.B10 D418.B11 D418.B12 D418.B13 D418.B14 D418.B15 D418.B16 D419.A1 D419.A2 D419.A3 D419.A4 D419.A5 D419.A6 D419.A7 D419.A8 D419.A9 D419.A10 D419.A11 D419.A12 D419.A13 D419.A14 D419.A15 D419.A16 D419.B1 D419.B2 D419.B3 D419.B4 D419.B5 D419.B6 D419.B7 D419.B8 D419.B9 D419.B10 D419.B11 D419.B12 D419.B13 D419.B14 D419.B15 D419.B16 D420.A1 D420.A2 D420.A3 D420.A4 D420.A5 D420.A6 D420.A7 D420.A8 D420.A9 D420.A10 D420.A11 D420.A12 D420.A13 D420.A14 D420.A15 D420.A16 D420.B1 D420.B2 D420.B3 D420.B4 D420.B5 D420.B6 D420.B7 D420.B8 D420.B9 D420.B10 D420.B11 D420.B12 D420.B13 D420.B14 D420.B15 D420.B16 D421.A1 D421.A2 D421.A3 D421.A4 D421.A5 D421.A6 D421.A7 D421.A8 D421.A9 D421.A10 D421.A11 D421.A12 D421.A13 D421.A14 D421.A15 D421.A16 D421.B1 D421.B2 D421.B3 D421.B4 D421.B5 D421.B6 D421.B7 D421.B8 D421.B9 D421.B10 D421.B11 D421.B12 D421.B13 D421.B14 D421.B15 D421.B16 D422.A1 D422.A2 D422.A3 D422.A4 D422.A5 D422.A6 D422.A7 D422.A8 D422.A9 D422.A10 D422.A11 D422.A12 D422.A13 D422.A14 D422.A15 D422.A16 D422.B1 D422.B2 D422.B3 D422.B4 D422.B5 D422.B6 D422.B7 D422.B8 D422.B9 D422.B10 D422.B11 D422.B12 D422.B13 D422.B14 D422.B15 D422.B16 D423.A1 D423.A2 D423.A3 D423.A4 D423.A5 D423.A6 D423.A7 D423.A8 D423.A9 D423.A10 D423.A11 D423.A12 D423.A13 D423.A14 D423.A15 D423.A16 D423.B1 D423.B2 D423.B3 D423.B4 D423.B5 D423.B6 D423.B7 D423.B8 D423.B9 D423.B10 D423.B11 D423.B12 D423.B13 D423.B14 D423.B15 D423.B16 D424.A1 D424.A2 D424.A3 D424.A4 D424.A5 D424.A6 D424.A7 D424.A8 D424.A9 D424.A10 D424.A11 D424.A12 D424.A13 D424.A14 D424.A15 D424.A16 D424.B1 D424.B2 D424.B3 D424.B4 D424.B5 D424.B6 D424.B7 D424.B8 D424.B9 D424.B10 D424.B11 D424.B12 D424.B13 D424.B14 D424.B15 D424.B16 UT5_SW1.9 UT5_SW1.10 UT5_SW1.11 UT5_SW1.12 UT5_SW1.13 UT5_SW1.14 UT5_SW1.15 UT5_SW1.16 UT5_SW2.9 UT5_SW2.10 UT5_SW2.11 UT5_SW2.12 UT5_SW2.13 UT5_SW2.14 UT5_SW2.15 UT5_SW2.16 UT6_SW1.9 UT6_SW1.10 UT6_SW1.11 UT6_SW1.12 UT6_SW1.13 UT6_SW1.14 UT6_SW1.15 UT6_SW1.16 UT6_SW2.9 UT6_SW2.10 UT6_SW2.11 UT6_SW2.12 UT6_SW2.13 UT6_SW2.14 UT6_SW2.15 UT6_SW2.16 UT7_SW1.9 UT7_SW1.10 UT7_SW1.11 UT7_SW1.12 UT7_SW1.13 UT7_SW1.14 UT7_SW1.15 UT7_SW1.16 UT7_SW2.9 UT7_SW2.10 UT7_SW2.11 UT7_SW2.12 UT7_SW2.13 UT7_SW2.14 UT7_SW2.15 UT7_SW2.16 UT8_SW1.9 UT8_SW1.10 UT8_SW1.11 UT8_SW1.12 UT8_SW1.13 UT8_SW1.14 UT8_SW1.15 UT8_SW1.16 UT8_SW2.9 UT8_SW2.10 UT8_SW2.11 UT8_SW2.12 UT8_SW2.13 UT8_SW2.14 UT8_SW2.15 UT8_SW2.16 ; also on sheet 1 2 3 4 5 6 7 8 9 10 11 12 13 14 17 18 19 20 21 22 23 24 30 31 32 33 34 35 36 37
D12501: D125.01
D12502: D125.02
D12503: D125.03
D12504: D125.04
D12505: D125.05
D12506: D125.06
D12507: D125.07
D12508: D125.08
D12509: D125.09
D12510: D125.10
D12511: D125.11
D12512: D125.12
D12513: D125.13
D12514: D125.14
D12515: D125.15
D12516: D125.16
D12601: D126.01
D12602: D126.02
D12603: D126.03
D12604: D126.04
D12605: D126.05
D12606: D126.06
D12607: D126.07
D12608: D126.08
D12609: D126.09
D12610: D126.10
D12611: D126.11
D12612: D126.12
D12613: D126.13
D12614: D126.14
D12615: D126.15
D12616: D126.16
D12701: D127.01
D12702: D127.02
D12703: D127.03
D12704: D127.04
D12705: D127.05
D12706: D127.06
D12707: D127.07
D12708: D127.08
D12709: D127.09
D12710: D127.10
D12711: D127.11
D12712: D127.12
D12713: D127.13
D12714: D127.14
D12715: D127.15
D12716: D127.16
D12801: D128.01
D12802: D128.02
D12803: D128.03
D12804: D128.04
D12805: D128.05
D12806: D128.06
D12807: D128.07
D12808: D128.08
D12809: D128.09
D12810: D128.10
D12811: D128.11
D12812: D128.12
D12813: D128.13
D12814: D128.14
D12815: D128.15
D12816: D128.16
D12901: D129.01
D12902: D129.02
D12903: D129.03
D12904: D129.04
D12905: D129.05
D12906: D129.06
D12907: D129.07
D12908: D129.08
D12909: D129.09
D12910: D129.10
D12911: D129.11
D12912: D129.12
D12913: D129.13
D12914: D129.14
D12915: D129.15
D12916: D129.16
D13001: D130.01
D13002: D130.02
D13003: D130.03
D13004: D130.04
D13005: D130.05
D13006: D130.06
D13007: D130.07
D13008: D130.08
D13009: D130.09
D13010: D130.10
D13011: D130.11
D13012: D130.12
D13013: D130.13
D13014: D130.14
D13015: D130.15
D13016: D130.16
D13101: D131.01
D13102: D131.02
D13103: D131.03
D13104: D131.04
D13105: D131.05
D13106: D131.06
D13107: D131.07
D13108: D131.08
D13109: D131.09
D13110: D131.10
D13111: D131.11
D13112: D131.12
D13113: D131.13
D13114: D131.14
D13115: D131.15
D13116: D131.16
D13201: D132.01
D13202: D132.02
D13203: D132.03
D13204: D132.04
D13205: D132.05
D13206: D132.06
D13207: D132.07
D13208: D132.08
D13209: D132.09
D13210: D132.10
D13211: D132.11
D13212: D132.12
D13213: D132.13
D13214: D132.14
D13215: D132.15
D13216: D132.16
D20101: D201.01
D20102: D201.02
D20103: D201.03
D20104: D201.04
D20105: D201.05
D20106: D201.06
D20107: D201.07
D20108: D201.08
D20109: D201.09
D20110: D201.10
D20111: D201.11
D20112: D201.12
D20113: D201.13
D20114: D201.14
D20115: D201.15
D20116: D201.16
D20201: D202.01
D20202: D202.02
D20203: D202.03
D20204: D202.04
D20205: D202.05
D20206: D202.06
D20207: D202.07
D20208: D202.08
D20209: D202.09
D20210: D202.10
D20211: D202.11
D20212: D202.12
D20213: D202.13
D20214: D202.14
D20215: D202.15
D20216: D202.16
D20301: D203.01
D20302: D203.02
D20303: D203.03
D20304: D203.04
D20305: D203.05
D20306: D203.06
D20307: D203.07
D20308: D203.08
D20309: D203.09
D20310: D203.10
D20311: D203.11
D20312: D203.12
D20313: D203.13
D20314: D203.14
D20315: D203.15
D20316: D203.16
D20401: D204.01
D20402: D204.02
D20403: D204.03
D20404: D204.04
D20405: D204.05
D20406: D204.06
D20407: D204.07
D20408: D204.08
D20409: D204.09
D20410: D204.10
D20411: D204.11
D20412: D204.12
D20413: D204.13
D20414: D204.14
D20415: D204.15
D20416: D204.16
D20501: D205.01
D20502: D205.02
D20503: D205.03
D20504: D205.04
D20505: D205.05
D20506: D205.06
D20507: D205.07
D20508: D205.08
D20509: D205.09
D20510: D205.10
D20511: D205.11
D20512: D205.12
D20513: D205.13
D20514: D205.14
D20515: D205.15
D20516: D205.16
D20601: D206.01
D20602: D206.02
D20603: D206.03
D20604: D206.04
D20605: D206.05
D20606: D206.06
D20607: D206.07
D20608: D206.08
D20609: D206.09
D20610: D206.10
D20611: D206.11
D20612: D206.12
D20613: D206.13
D20614: D206.14
D20615: D206.15
D20616: D206.16
D20701: D207.01
D20702: D207.02
D20703: D207.03
D20704: D207.04
D20705: D207.05
D20706: D207.06
D20707: D207.07
D20708: D207.08
D20709: D207.09
D20710: D207.10
D20711: D207.11
D20712: D207.12
D20713: D207.13
D20714: D207.14
D20715: D207.15
D20716: D207.16
D20801: D208.01
D20802: D208.02
D20803: D208.03
D20804: D208.04
D20805: D208.05
D20806: D208.06
D20807: D208.07
D20808: D208.08
D20809: D208.09
D20810: D208.10
D20811: D208.11
D20812: D208.12
D20813: D208.13
D20814: D208.14
D20815: D208.15
D20816: D208.16
D20901: D209.01
D20902: D209.02
D20903: D209.03
D20904: D209.04
D20905: D209.05
D20906: D209.06
D20907: D209.07
D20908: D209.08
D20909: D209.09
D20910: D209.10
D20911: D209.11
D20912: D209.12
D20913: D209.13
D20914: D209.14
D20915: D209.15
D20916: D209.16
D21001: D210.01
D21002: D210.02
D21003: D210.03
D21004: D210.04
D21005: D210.05
D21006: D210.06
D21007: D210.07
D21008: D210.08
D21009: D210.09
D21010: D210.10
D21011: D210.11
D21012: D210.12
D21013: D210.13
D21014: D210.14
D21015: D210.15
D21016: D210.16
D21101: D211.01
D21102: D211.02
D21103: D211.03
D21104: D211.04
D21105: D211.05
D21106: D211.06
D21107: D211.07
D21108: D211.08
D21109: D211.09
D21110: D211.10
D21111: D211.11
D21112: D211.12
D21113: D211.13
D21114: D211.14
D21115: D211.15
D21116: D211.16
D21201: D212.01
D21202: D212.02
D21203: D212.03
D21204: D212.04
D21205: D212.05
D21206: D212.06
D21207: D212.07
D21208: D212.08
D21209: D212.09
D21210: D212.10
D21211: D212.11
D21212: D212.12
D21213: D212.13
D21214: D212.14
D21215: D212.15
D21216: D212.16
D21301: D213.01
D21302: D213.02
D21303: D213.03
D21304: D213.04
D21305: D213.05
D21306: D213.06
D21307: D213.07
D21308: D213.08
D21309: D213.09
D21310: D213.10
D21311: D213.11
D21312: D213.12
D21313: D213.13
D21314: D213.14
D21315: D213.15
D21316: D213.16
D21401: D214.01
D21402: D214.02
D21403: D214.03
D21404: D214.04
D21405: D214.05
D21406: D214.06
D21407: D214.07
D21408: D214.08
D21409: D214.09
D21410: D214.10
D21411: D214.11
D21412: D214.12
D21413: D214.13
D21414: D214.14
D21415: D214.15
D21416: D214.16
D21501: D215.01
D21502: D215.02
D21503: D215.03
D21504: D215.04
D21505: D215.05
D21506: D215.06
D21507: D215.07
D21508: D215.08
D21509: D215.09
D21510: D215.10
D21511: D215.11
D21512: D215.12
D21513: D215.13
D21514: D215.14
D21515: D215.15
D21516: D215.16
D21601: D216.01
D21602: D216.02
D21603: D216.03
D21604: D216.04
D21605: D216.05
D21606: D216.06
D21607: D216.07
D21608: D216.08
D21609: D216.09
D21610: D216.10
D21611: D216.11
D21612: D216.12
D21613: D216.13
D21614: D216.14
D21615: D216.15
D21616: D216.16
D21701: D217.01
D21702: D217.02
D21703: D217.03
D21704: D217.04
D21705: D217.05
D21706: D217.06
D21707: D217.07
D21708: D217.08
D21709: D217.09
D21710: D217.10
D21711: D217.11
D21712: D217.12
D21713: D217.13
D21714: D217.14
D21715: D217.15
D21716: D217.16
D21801: D218.01
D21802: D218.02
D21803: D218.03
D21804: D218.04
D21805: D218.05
D21806: D218.06
D21807: D218.07
D21808: D218.08
D21809: D218.09
D21810: D218.10
D21811: D218.11
D21812: D218.12
D21813: D218.13
D21814: D218.14
D21815: D218.15
D21816: D218.16
D21901: D219.01
D21902: D219.02
D21903: D219.03
D21904: D219.04
D21905: D219.05
D21906: D219.06
D21907: D219.07
D21908: D219.08
D21909: D219.09
D21910: D219.10
D21911: D219.11
D21912: D219.12
D21913: D219.13
D21914: D219.14
D21915: D219.15
D21916: D219.16
D22001: D220.01
D22002: D220.02
D22003: D220.03
D22004: D220.04
D22005: D220.05
D22006: D220.06
D22007: D220.07
D22008: D220.08
D22009: D220.09
D22010: D220.10
D22011: D220.11
D22012: D220.12
D22013: D220.13
D22014: D220.14
D22015: D220.15
D22016: D220.16
D22101: D221.01
D22102: D221.02
D22103: D221.03
D22104: D221.04
D22105: D221.05
D22106: D221.06
D22107: D221.07
D22108: D221.08
D22109: D221.09
D22110: D221.10
D22111: D221.11
D22112: D221.12
D22113: D221.13
D22114: D221.14
D22115: D221.15
D22116: D221.16
D22201: D222.01
D22202: D222.02
D22203: D222.03
D22204: D222.04
D22205: D222.05
D22206: D222.06
D22207: D222.07
D22208: D222.08
D22209: D222.09
D22210: D222.10
D22211: D222.11
D22212: D222.12
D22213: D222.13
D22214: D222.14
D22215: D222.15
D22216: D222.16
D22301: D223.01
D22302: D223.02
D22303: D223.03
D22304: D223.04
D22305: D223.05
D22306: D223.06
D22307: D223.07
D22308: D223.08
D22309: D223.09
D22310: D223.10
D22311: D223.11
D22312: D223.12
D22313: D223.13
D22314: D223.14
D22315: D223.15
D22316: D223.16
D22401: D224.01
D22402: D224.02
D22403: D224.03
D22404: D224.04
D22405: D224.05
D22406: D224.06
D22407: D224.07
D22408: D224.08
D22409: D224.09
D22410: D224.10
D22411: D224.11
D22412: D224.12
D22413: D224.13
D22414: D224.14
D22415: D224.15
D22416: D224.16
D32501: D325.01
D32502: D325.02
D32503: D325.03
D32504: D325.04
D32505: D325.05
D32506: D325.06
D32507: D325.07
D32508: D325.08
D32509: D325.09
D32510: D325.10
D32511: D325.11
D32512: D325.12
D32513: D325.13
D32514: D325.14
D32515: D325.15
D32516: D325.16
D32601: D326.01
D32602: D326.02
D32603: D326.03
D32604: D326.04
D32605: D326.05
D32606: D326.06
D32607: D326.07
D32608: D326.08
D32609: D326.09
D32610: D326.10
D32611: D326.11
D32612: D326.12
D32613: D326.13
D32614: D326.14
D32615: D326.15
D32616: D326.16
D32701: D327.01
D32702: D327.02
D32703: D327.03
D32704: D327.04
D32705: D327.05
D32706: D327.06
D32707: D327.07
D32708: D327.08
D32709: D327.09
D32710: D327.10
D32711: D327.11
D32712: D327.12
D32713: D327.13
D32714: D327.14
D32715: D327.15
D32716: D327.16
D32801: D328.01
D32802: D328.02
D32803: D328.03
D32804: D328.04
D32805: D328.05
D32806: D328.06
D32807: D328.07
D32808: D328.08
D32809: D328.09
D32810: D328.10
D32811: D328.11
D32812: D328.12
D32813: D328.13
D32814: D328.14
D32815: D328.15
D32816: D328.16
D32901: D329.01
D32902: D329.02
D32903: D329.03
D32904: D329.04
D32905: D329.05
D32906: D329.06
D32907: D329.07
D32908: D329.08
D32909: D329.09
D32910: D329.10
D32911: D329.11
D32912: D329.12
D32913: D329.13
D32914: D329.14
D32915: D329.15
D32916: D329.16
D33001: D330.01
D33002: D330.02
D33003: D330.03
D33004: D330.04
D33005: D330.05
D33006: D330.06
D33007: D330.07
D33008: D330.08
D33009: D330.09
D33010: D330.10
D33011: D330.11
D33012: D330.12
D33013: D330.13
D33014: D330.14
D33015: D330.15
D33016: D330.16
D33101: D331.01
D33102: D331.02
D33103: D331.03
D33104: D331.04
D33105: D331.05
D33106: D331.06
D33107: D331.07
D33108: D331.08
D33109: D331.09
D33110: D331.10
D33111: D331.11
D33112: D331.12
D33113: D331.13
D33114: D331.14
D33115: D331.15
D33116: D331.16
D33201: D332.01
D33202: D332.02
D33203: D332.03
D33204: D332.04
D33205: D332.05
D33206: D332.06
D33207: D332.07
D33208: D332.08
D33209: D332.09
D33210: D332.10
D33211: D332.11
D33212: D332.12
D33213: D332.13
D33214: D332.14
D33215: D332.15
D33216: D332.16
D40901: D409.01
D40902: D409.02
D40903: D409.03
D40904: D409.04
D40905: D409.05
D40906: D409.06
D40907: D409.07
D40908: D409.08
D40909: D409.09
D40910: D409.10
D40911: D409.11
D40912: D409.12
D40913: D409.13
D40914: D409.14
D40915: D409.15
D40916: D409.16
D41001: D410.01
D41002: D410.02
D41003: D410.03
D41004: D410.04
D41005: D410.05
D41006: D410.06
D41007: D410.07
D41008: D410.08
D41009: D410.09
D41010: D410.10
D41011: D410.11
D41012: D410.12
D41013: D410.13
D41014: D410.14
D41015: D410.15
D41016: D410.16
D41101: D411.01
D41102: D411.02
D41103: D411.03
D41104: D411.04
D41105: D411.05
D41106: D411.06
D41107: D411.07
D41108: D411.08
D41109: D411.09
D41110: D411.10
D41111: D411.11
D41112: D411.12
D41113: D411.13
D41114: D411.14
D41115: D411.15
D41116: D411.16
D41201: D412.01
D41202: D412.02
D41203: D412.03
D41204: D412.04
D41205: D412.05
D41206: D412.06
D41207: D412.07
D41208: D412.08
D41209: D412.09
D41210: D412.10
D41211: D412.11
D41212: D412.12
D41213: D412.13
D41214: D412.14
D41215: D412.15
D41216: D412.16
D41301: D413.01
D41302: D413.02
D41303: D413.03
D41304: D413.04
D41305: D413.05
D41306: D413.06
D41307: D413.07
D41308: D413.08
D41309: D413.09
D41310: D413.10
D41311: D413.11
D41312: D413.12
D41313: D413.13
D41314: D413.14
D41315: D413.15
D41316: D413.16
D41401: D414.01
D41402: D414.02
D41403: D414.03
D41404: D414.04
D41405: D414.05
D41406: D414.06
D41407: D414.07
D41408: D414.08
D41409: D414.09
D41410: D414.10
D41411: D414.11
D41412: D414.12
D41413: D414.13
D41414: D414.14
D41415: D414.15
D41416: D414.16
D41501: D415.01
D41502: D415.02
D41503: D415.03
D41504: D415.04
D41505: D415.05
D41506: D415.06
D41507: D415.07
D41508: D415.08
D41509: D415.09
D41510: D415.10
D41511: D415.11
D41512: D415.12
D41513: D415.13
D41514: D415.14
D41515: D415.15
D41516: D415.16
D41601: D416.01
D41602: D416.02
D41603: D416.03
D41604: D416.04
D41605: D416.05
D41606: D416.06
D41607: D416.07
D41608: D416.08
D41609: D416.09
D41610: D416.10
D41611: D416.11
D41612: D416.12
D41613: D416.13
D41614: D416.14
D41615: D416.15
D41616: D416.16
D41701: D417.01
D41702: D417.02
D41703: D417.03
D41704: D417.04
D41705: D417.05
D41706: D417.06
D41707: D417.07
D41708: D417.08
D41709: D417.09
D41710: D417.10
D41711: D417.11
D41712: D417.12
D41713: D417.13
D41714: D417.14
D41715: D417.15
D41716: D417.16
D41801: D418.01
D41802: D418.02
D41803: D418.03
D41804: D418.04
D41805: D418.05
D41806: D418.06
D41807: D418.07
D41808: D418.08
D41809: D418.09
D41810: D418.10
D41811: D418.11
D41812: D418.12
D41813: D418.13
D41814: D418.14
D41815: D418.15
D41816: D418.16
D41901: D419.01
D41902: D419.02
D41903: D419.03
D41904: D419.04
D41905: D419.05
D41906: D419.06
D41907: D419.07
D41908: D419.08
D41909: D419.09
D41910: D419.10
D41911: D419.11
D41912: D419.12
D41913: D419.13
D41914: D419.14
D41915: D419.15
D41916: D419.16
D42001: D420.01
D42002: D420.02
D42003: D420.03
D42004: D420.04
D42005: D420.05
D42006: D420.06
D42007: D420.07
D42008: D420.08
D42009: D420.09
D42010: D420.10
D42011: D420.11
D42012: D420.12
D42013: D420.13
D42014: D420.14
D42015: D420.15
D42016: D420.16
D42101: D421.01
D42102: D421.02
D42103: D421.03
D42104: D421.04
D42105: D421.05
D42106: D421.06
D42107: D421.07
D42108: D421.08
D42109: D421.09
D42110: D421.10
D42111: D421.11
D42112: D421.12
D42113: D421.13
D42114: D421.14
D42115: D421.15
D42116: D421.16
D42201: D422.01
D42202: D422.02
D42203: D422.03
D42204: D422.04
D42205: D422.05
D42206: D422.06
D42207: D422.07
D42208: D422.08
D42209: D422.09
D42210: D422.10
D42211: D422.11
D42212: D422.12
D42213: D422.13
D42214: D422.14
D42215: D422.15
D42216: D422.16
D42301: D423.01
D42302: D423.02
D42303: D423.03
D42304: D423.04
D42305: D423.05
D42306: D423.06
D42307: D423.07
D42308: D423.08
D42309: D423.09
D42310: D423.10
D42311: D423.11
D42312: D423.12
D42313: D423.13
D42314: D423.14
D42315: D423.15
D42316: D423.16
D42401: D424.01
D42402: D424.02
D42403: D424.03
D42404: D424.04
D42405: D424.05
D42406: D424.06
D42407: D424.07
D42408: D424.08
D42409: D424.09
D42410: D424.10
D42411: D424.11
D42412: D424.12
D42413: D424.13
D42414: D424.14
D42415: D424.15
D42416: D424.16
UDBGND: CB9.2 CB10.2 CB11.2 CB12.2 CB13.2 CB14.2 CB15.2 CB16.2 UTL5.A02 UTL5.A08 UTL5.A10 UTL5.A12 UTL5.A14 UTL5.B01 UTL5.B07 UTL5.B09 UTL5.B11 UTL5.B13 UTL6.A02 UTL6.A08 UTL6.A10 UTL6.A12 UTL6.A14 UTL6.B01 UTL6.B07 UTL6.B09 UTL6.B11 UTL6.B13 UTL7.A02 UTL7.A08 UTL7.A10 UTL7.A12 UTL7.A14 UTL7.B01 UTL7.B07 UTL7.B09 UTL7.B11 UTL7.B13 UTL8.A02 UTL8.A08 UTL8.A10 UTL8.A12 UTL8.A14 UTL8.B01 UTL8.B07 UTL8.B09 UTL8.B11 UTL8.B13 ; also on sheet 20 21 22 23 24
UT1_UP5V: CB9.1 CB10.1 CB11.1 CB12.1 CB13.1 CB14.1 CB15.1 CB16.1 UTL5.A05 UTL5.B04 UTL6.A05 UTL6.B04 UTL7.A05 UTL7.B04 UTL8.A05 UTL8.B04 ; also on sheet 2 4 6 8 10 12 14 17 19 20 21 22 23 24 30 31 32 33 34 35 36 37
UT5_PDCF: UTL5.B15
UT5_PDCS: UTL5.A15
UT5_PGDS: UTL5.A16
UT5_PGRD: UTL5.B16
UT5_UW00: UT5_SW1.8 UTL5.A01
UT5_UW01: UT5_SW1.7 UTL5.B02
UT5_UW02: UT5_SW1.6 UTL5.A03
UT5_UW03: UT5_SW1.5 UTL5.B03
UT5_UW04: UT5_SW1.4 UTL5.A04
UT5_UW05: UT5_SW1.3 UTL5.B05
UT5_UW06: UT5_SW1.2 UTL5.A06
UT5_UW07: UT5_SW1.1 UTL5.B06
UT5_UW08: UT5_SW2.8 UTL5.A07
UT5_UW09: UT5_SW2.7 UTL5.B08
UT5_UW10: UT5_SW2.6 UTL5.A09
UT5_UW11: UT5_SW2.5 UTL5.B10
UT5_UW12: UT5_SW2.4 UTL5.A11
UT5_UW13: UT5_SW2.3 UTL5.B12
UT5_UW14: UT5_SW2.2 UTL5.A13
UT5_UW15: UT5_SW2.1 UTL5.B14
UT6_PDCF: UTL6.B15
UT6_PDCS: UTL6.A15
UT6_PGDS: UTL6.A16
UT6_PGRD: UTL6.B16
UT6_UW00: UT6_SW1.8 UTL6.A01
UT6_UW01: UT6_SW1.7 UTL6.B02
UT6_UW02: UT6_SW1.6 UTL6.A03
UT6_UW03: UT6_SW1.5 UTL6.B03
UT6_UW04: UT6_SW1.4 UTL6.A04
UT6_UW05: UT6_SW1.3 UTL6.B05
UT6_UW06: UT6_SW1.2 UTL6.A06
UT6_UW07: UT6_SW1.1 UTL6.B06
UT6_UW08: UT6_SW2.8 UTL6.A07
UT6_UW09: UT6_SW2.7 UTL6.B08
UT6_UW10: UT6_SW2.6 UTL6.A09
UT6_UW11: UT6_SW2.5 UTL6.B10
UT6_UW12: UT6_SW2.4 UTL6.A11
UT6_UW13: UT6_SW2.3 UTL6.B12
UT6_UW14: UT6_SW2.2 UTL6.A13
UT6_UW15: UT6_SW2.1 UTL6.B14
UT7_PDCF: UTL7.B15
UT7_PDCS: UTL7.A15
UT7_PGDS: UTL7.A16
UT7_PGRD: UTL7.B16
UT7_UW00: UT7_SW1.8 UTL7.A01
UT7_UW01: UT7_SW1.7 UTL7.B02
UT7_UW02: UT7_SW1.6 UTL7.A03
UT7_UW03: UT7_SW1.5 UTL7.B03
UT7_UW04: UT7_SW1.4 UTL7.A04
UT7_UW05: UT7_SW1.3 UTL7.B05
UT7_UW06: UT7_SW1.2 UTL7.A06
UT7_UW07: UT7_SW1.1 UTL7.B06
UT7_UW08: UT7_SW2.8 UTL7.A07
UT7_UW09: UT7_SW2.7 UTL7.B08
UT7_UW10: UT7_SW2.6 UTL7.A09
UT7_UW11: UT7_SW2.5 UTL7.B10
UT7_UW12: UT7_SW2.4 UTL7.A11
UT7_UW13: UT7_SW2.3 UTL7.B12
UT7_UW14: UT7_SW2.2 UTL7.A13
UT7_UW15: UT7_SW2.1 UTL7.B14
UT8_PDCF: UTL8.B15
UT8_PDCS: UTL8.A15
UT8_PGDS: UTL8.A16
UT8_PGRD: UTL8.B16
UT8_UW00: UT8_SW1.8 UTL8.A01
UT8_UW01: UT8_SW1.7 UTL8.B02
UT8_UW02: UT8_SW1.6 UTL8.A03
UT8_UW03: UT8_SW1.5 UTL8.B03
UT8_UW04: UT8_SW1.4 UTL8.A04
UT8_UW05: UT8_SW1.3 UTL8.B05
UT8_UW06: UT8_SW1.2 UTL8.A06
UT8_UW07: UT8_SW1.1 UTL8.B06
UT8_UW08: UT8_SW2.8 UTL8.A07
UT8_UW09: UT8_SW2.7 UTL8.B08
UT8_UW10: UT8_SW2.6 UTL8.A09
UT8_UW11: UT8_SW2.5 UTL8.B10
UT8_UW12: UT8_SW2.4 UTL8.A11
UT8_UW13: UT8_SW2.3 UTL8.B12
UT8_UW14: UT8_SW2.2 UTL8.A13
UT8_UW15: UT8_SW2.1 UTL8.B14

Not connected (* = marked no-connect by the designer): 038XS-I6K51D18Q-A100 1*; 980XS-I6K51D-1AG- 1*; BGA293-9x7-P0.4 1*; D125 17* A17* B17*; D126 17* A17* B17*; D127 17* A17* B17*; D128 17* A17* B17*; D129 17* A17* B17*; D130 17* A17* B17*; D131 17* A17* B17*; D132 17* A17* B17*; D201 17* A17* B17*; D202 17* A17* B17*; D203 17* A17* B17*; D204 17* A17* B17*; D205 17* A17* B17*; D206 17* A17* B17*; D207 17* A17* B17*; D208 17* A17* B17*; D209 17* A17* B17*; D210 17* A17* B17*; D211 17* A17* B17*; D212 17* A17* B17*; D213 17* A17* B17*; D214 17* A17* B17*; D215 17* A17* B17*; D216 17* A17* B17*; D217 17* A17* B17*; D218 17* A17* B17*; D219 17* A17* B17*; D220 17* A17* B17*; D221 17* A17* B17*; D222 17* A17* B17*; D223 17* A17* B17*; D224 17* A17* B17*; D325 17* A17* B17*; D326 17* A17* B17*; D327 17* A17* B17*; D328 17* A17* B17*; D329 17* A17* B17*; D330 17* A17* B17*; D331 17* A17* B17*; D332 17* A17* B17*; D409 17* A17* B17*; D410 17* A17* B17*; D411 17* A17* B17*; D412 17* A17* B17*; D413 17* A17* B17*; D414 17* A17* B17*; D415 17* A17* B17*; D416 17* A17* B17*; D417 17* A17* B17*; D418 17* A17* B17*; D419 17* A17* B17*; D420 17* A17* B17*; D421 17* A17* B17*; D422 17* A17* B17*; D423 17* A17* B17*; D424 17* A17* B17*; FD1 1(FD)*; FD2 1(FD)*; FD3 1(FD)*; FD4 1(FD)*; FD5 1(FD)*; FD6 1(FD)*; FD7 1(FD)*; FD8 1(FD)*; FD9 1(FD)*; FD10 1(FD)*; FD11 1(FD)*; FD12 1(FD)*; FD13 1(FD)*; FD14 1(FD)*; FD15 1(FD)*; FD16 1(FD)*; H1 1(NP1)*; H2 1(NP1)*; H3 1(NP1)*; H4 1(NP1)*; JG261002WW011 1*; LOGO1 1*; LOGO2 1*; SCREW1 1* 2* 3* 4* 5* 6* 7* 8* 9* 10* 11* 12* 13* 14* 15* 16* 17* 18* 19* 20* 21* 22* 23* 24* 25* 26* 27* 28* 29* 30* 31* 32* GH1* GH2* GH3* GH4*; SSI6K51D 1*; UTL5 A17* B17*; UTL6 A17* B17*; UTL7 A17* B17*; UTL8 A17* B17*; VP1 1*

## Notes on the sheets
sheet 25
- GROUP4
- D129
- D329
- D130
- D330
- D131
- D331
- D132
- D332
- D125
- D325
- D126
- D326
- D127
- D327
- D128
- D328
sheet 26
- GROUP5
- D205
- D405
- D206
- D406
- D207
- D407
- D208
- D408
- D201
- D401
- D202
- D402
- D203
- D403
- D204
- D404
- MT6253
sheet 27
- GROUP6
- D213
- D413
- D214
- D414
- D215
- D415
- D216
- D416
- D209
- D409
- D210
- D410
- D211
- D411
- D212
- D412
sheet 28
- GROUP7
- D221
- D421
- D222
- D422
- D223
- D423
- D224
- D424
- D217
- D417
- D218
- D418
- D219
- D419
- D220
- D420
sheet 29
- SITE1
- SITE2
- SITE3
- SITE4
- SITE5
- SITE6
- SITE7
- SITE8
- Other
- 2 groups
  (6 traces)
- 2 groups
  (6 traces)
- 2 groups
  (6 traces)
- 2 groups
  (6 traces)
- 2 groups
  (6 traces)
- 2 groups
  (6 traces)
- 2 groups
  (6 traces)
- 2 groups
  (6 traces)
- CSDPS
- S*_PWR_M_F*
- Assign to D310, D314, D426, D430, D319, D323, D307, and D303.
  SITE1¡VSITE4 must be assigned to D310, D314, D426, and D430.
- CSDPS
- S*_PWR_F*
- 8 groups
  (24 traces)
- 8 groups
  (24 traces)
- 8 groups
  (24 traces)
- 8 groups
  (24 traces)
- 8 groups
  (24 traces)
- 8 groups
  (24 traces)
- 8 groups
  (24 traces)
- 8 groups
  (24 traces)
- S*_D_DCH*
- Diff100
- S*_DD_DCH*
- Diff90
- S*_B_DCH_*
- 3
- 3
- 3
- 3
- 3
- 3
- 3
- 3
- Trace Width: 20 mil
- S*_DCH*
- 23
- 23
- 23
- 23
- 23
- 23
- 23
- 23
- 1
- D101¡VD132, D201¡VD224, and D409¡VD416: 1024 channels available.
  SITE1¡VSITE4 must be assigned within D101¡VD132 and D201¡VD224 only.
- S*_MPDCH*
- 94
- 94
- 94
- 94
- 94
- 94
- 94
- 94
- S*_MPDCH* ¡V Memory Pulling Assignment Rules:
  1.SITE1 / SITE2 / SITE3 / SITE4 form one group.
  2.SITE5 / SITE6 / SITE7 / SITE8 form another group.
  3.Ball Assignments must be consecutive odd/even pairs
  (e.g., D10101 / D10102).
  4.If SITE1 / SITE2 / SITE3 / SITE4 are assigned to D121,
  SITE5 / SITE6 / SITE7 / SITE8 must NOT be assigned to D121.
- S*_ASCAN_*
- S*_BSCAN_*
- S*_ASCANA_*
- S*_BSCANB_*
- ASSIGN TO ASCANA
- ASSIGN TO BSCANB
- ASCANA: All 8 SITES must have equal trace lengths.
- *SX_MCB_0*
- 1
- 1
- 1
- 1
- X
- X
- X
- X
- Apply GND Shielding
- Assign to SA_RCBIT_*
- Relay Cbit
- *SA_CBIT_R*
- 13
- X
- X
- X
- 13
- X
- X
- X
- Assign to SA_SCBIT_*
- Switch Cbit
- *SA_CBIT_S*
- 13
- X
- X
- X
- 13
- X
- X
- X
- BF_RLY*
- 13
- X
- X
- X
- 13
- X
- X
- X
- BF_SW*
- 13
- X
- X
- X
- 13
- X
- X
- X
- SK_SW* has been assigned to UT1_UW14 and UT1_UW15.
  All U1¡VU8 channels are available except UT1_UW14 and UT1_UW15
- SK_RLY*
- 10
- SK_SW*
- 2
- M3*4
